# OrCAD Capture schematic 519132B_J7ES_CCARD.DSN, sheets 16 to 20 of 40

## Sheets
16 16. SOC PRG0 & PRG1: size C; rev: A
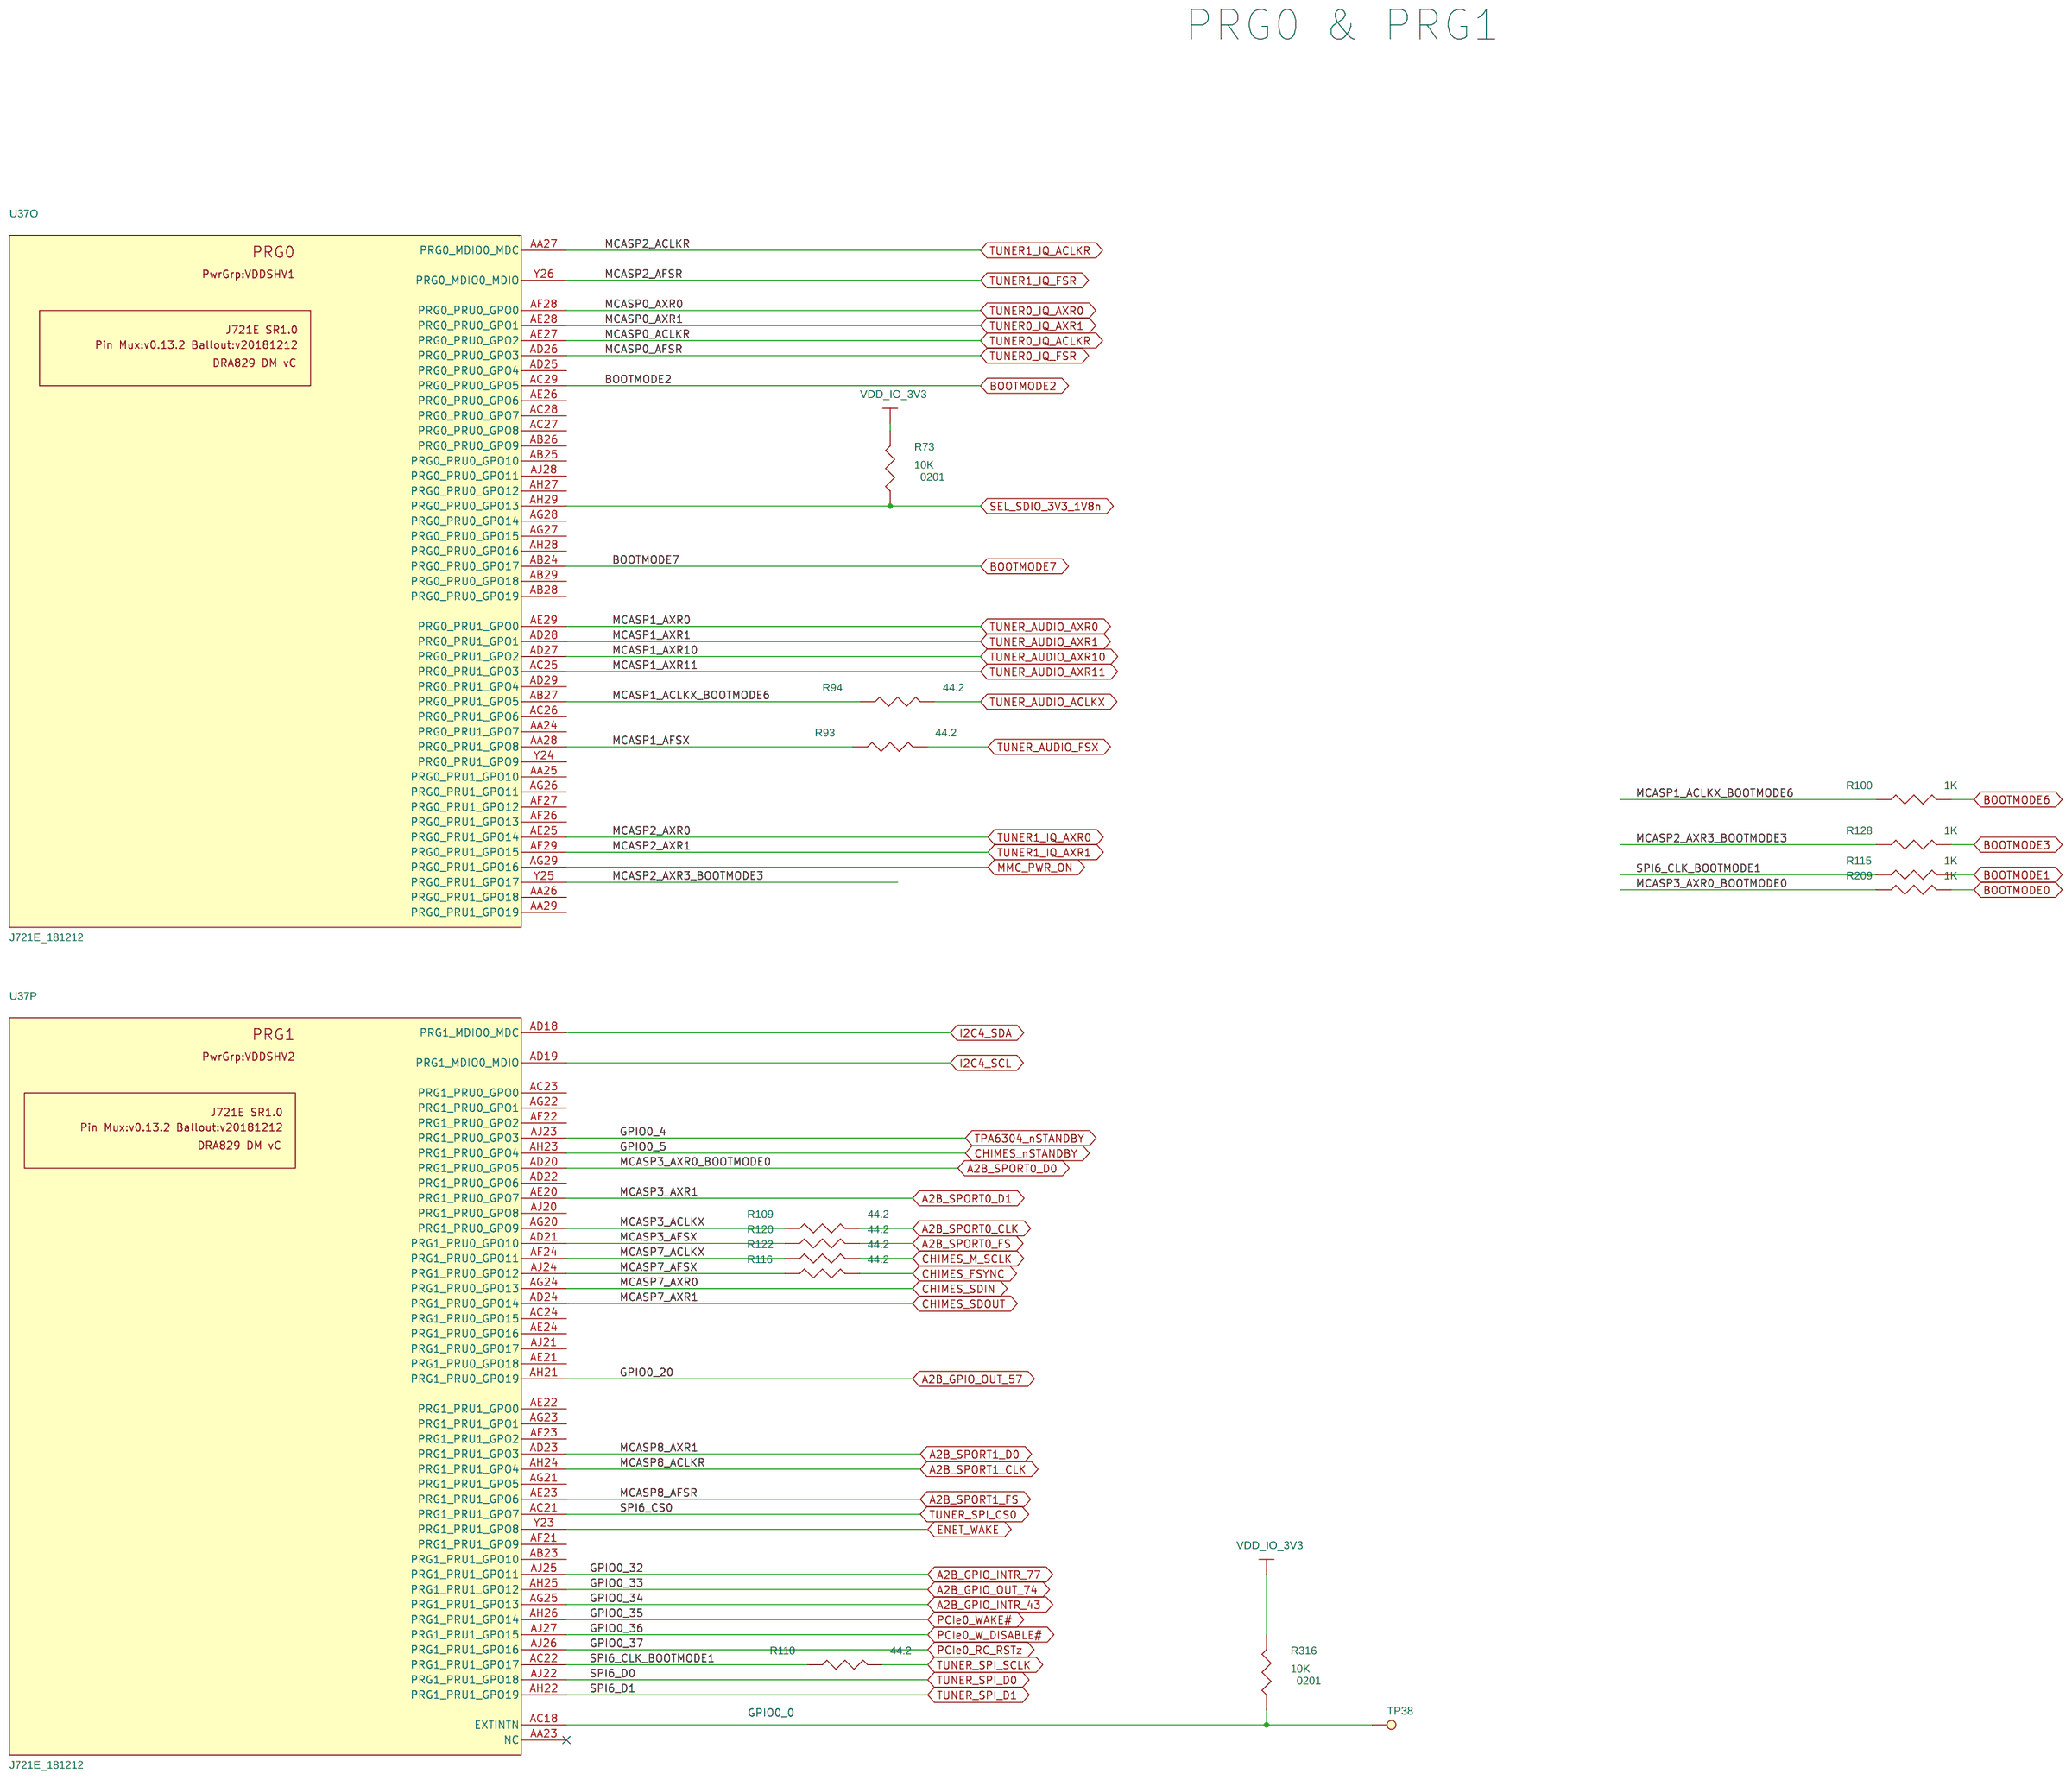
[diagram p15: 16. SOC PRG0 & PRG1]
17 17. SOC ANALOG POWER 1: size C; rev: A
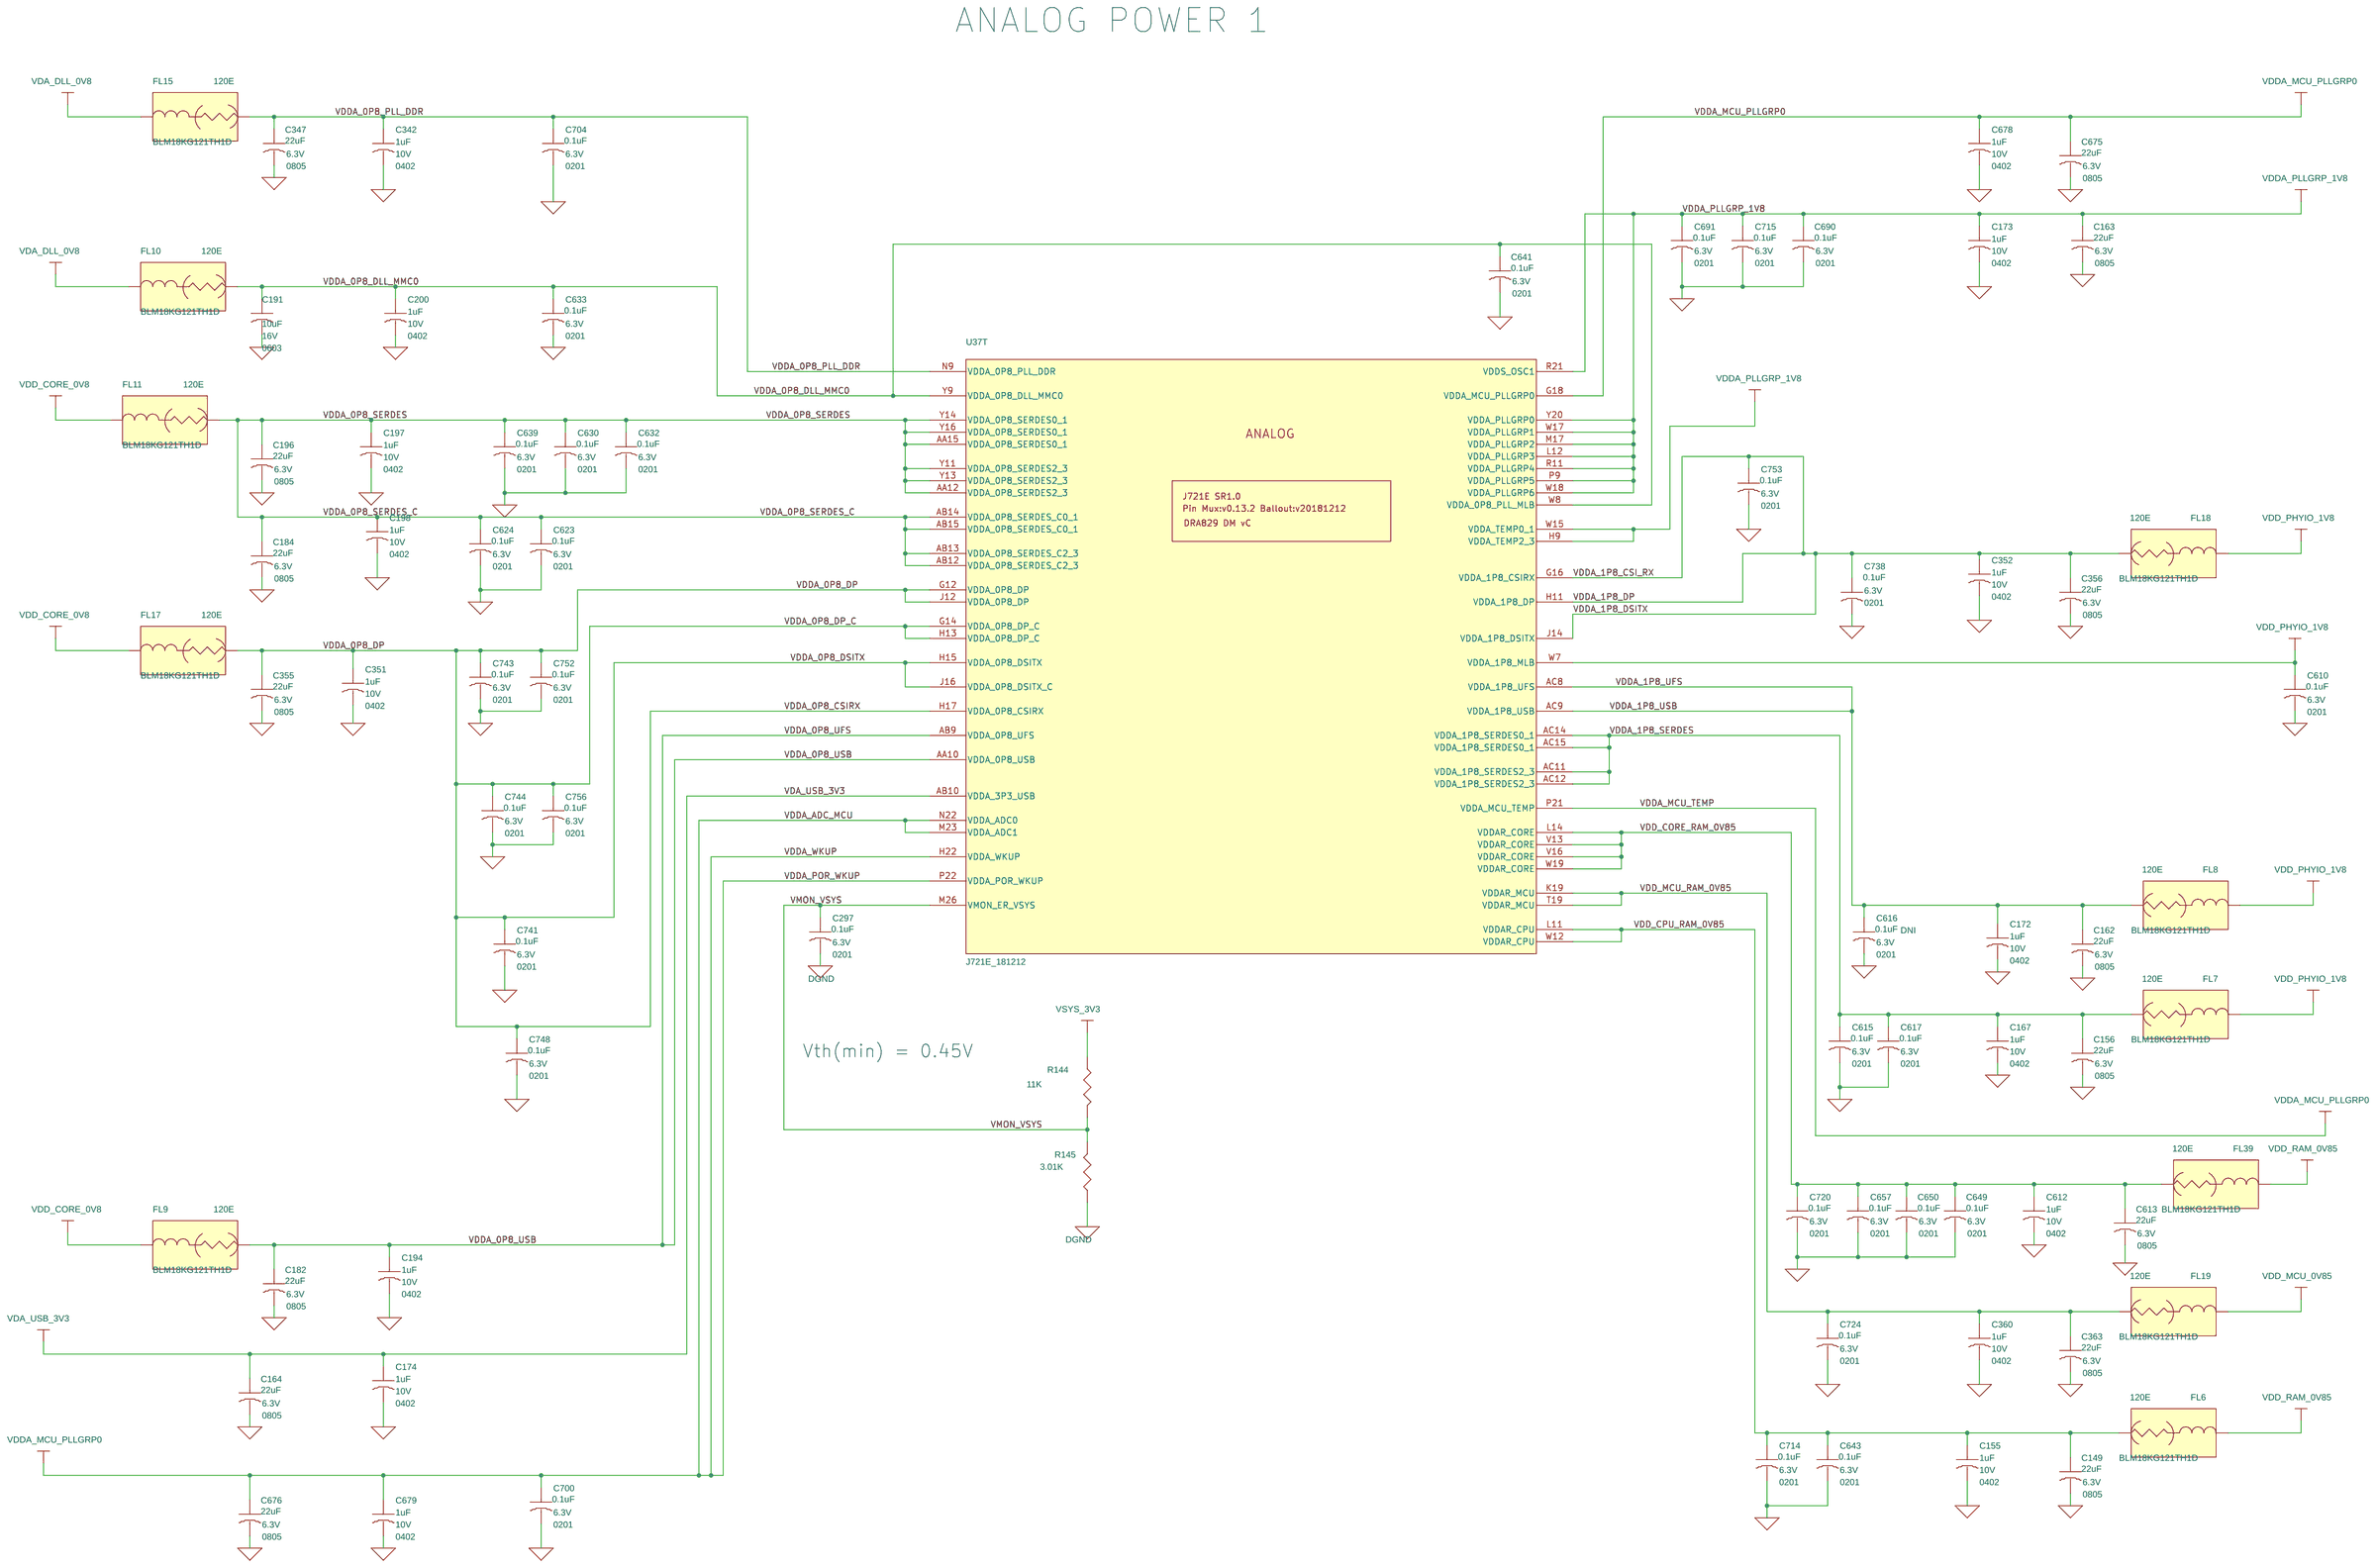
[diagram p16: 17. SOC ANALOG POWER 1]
18 18. SOC DIGITAL POWER 2: size C; rev: A
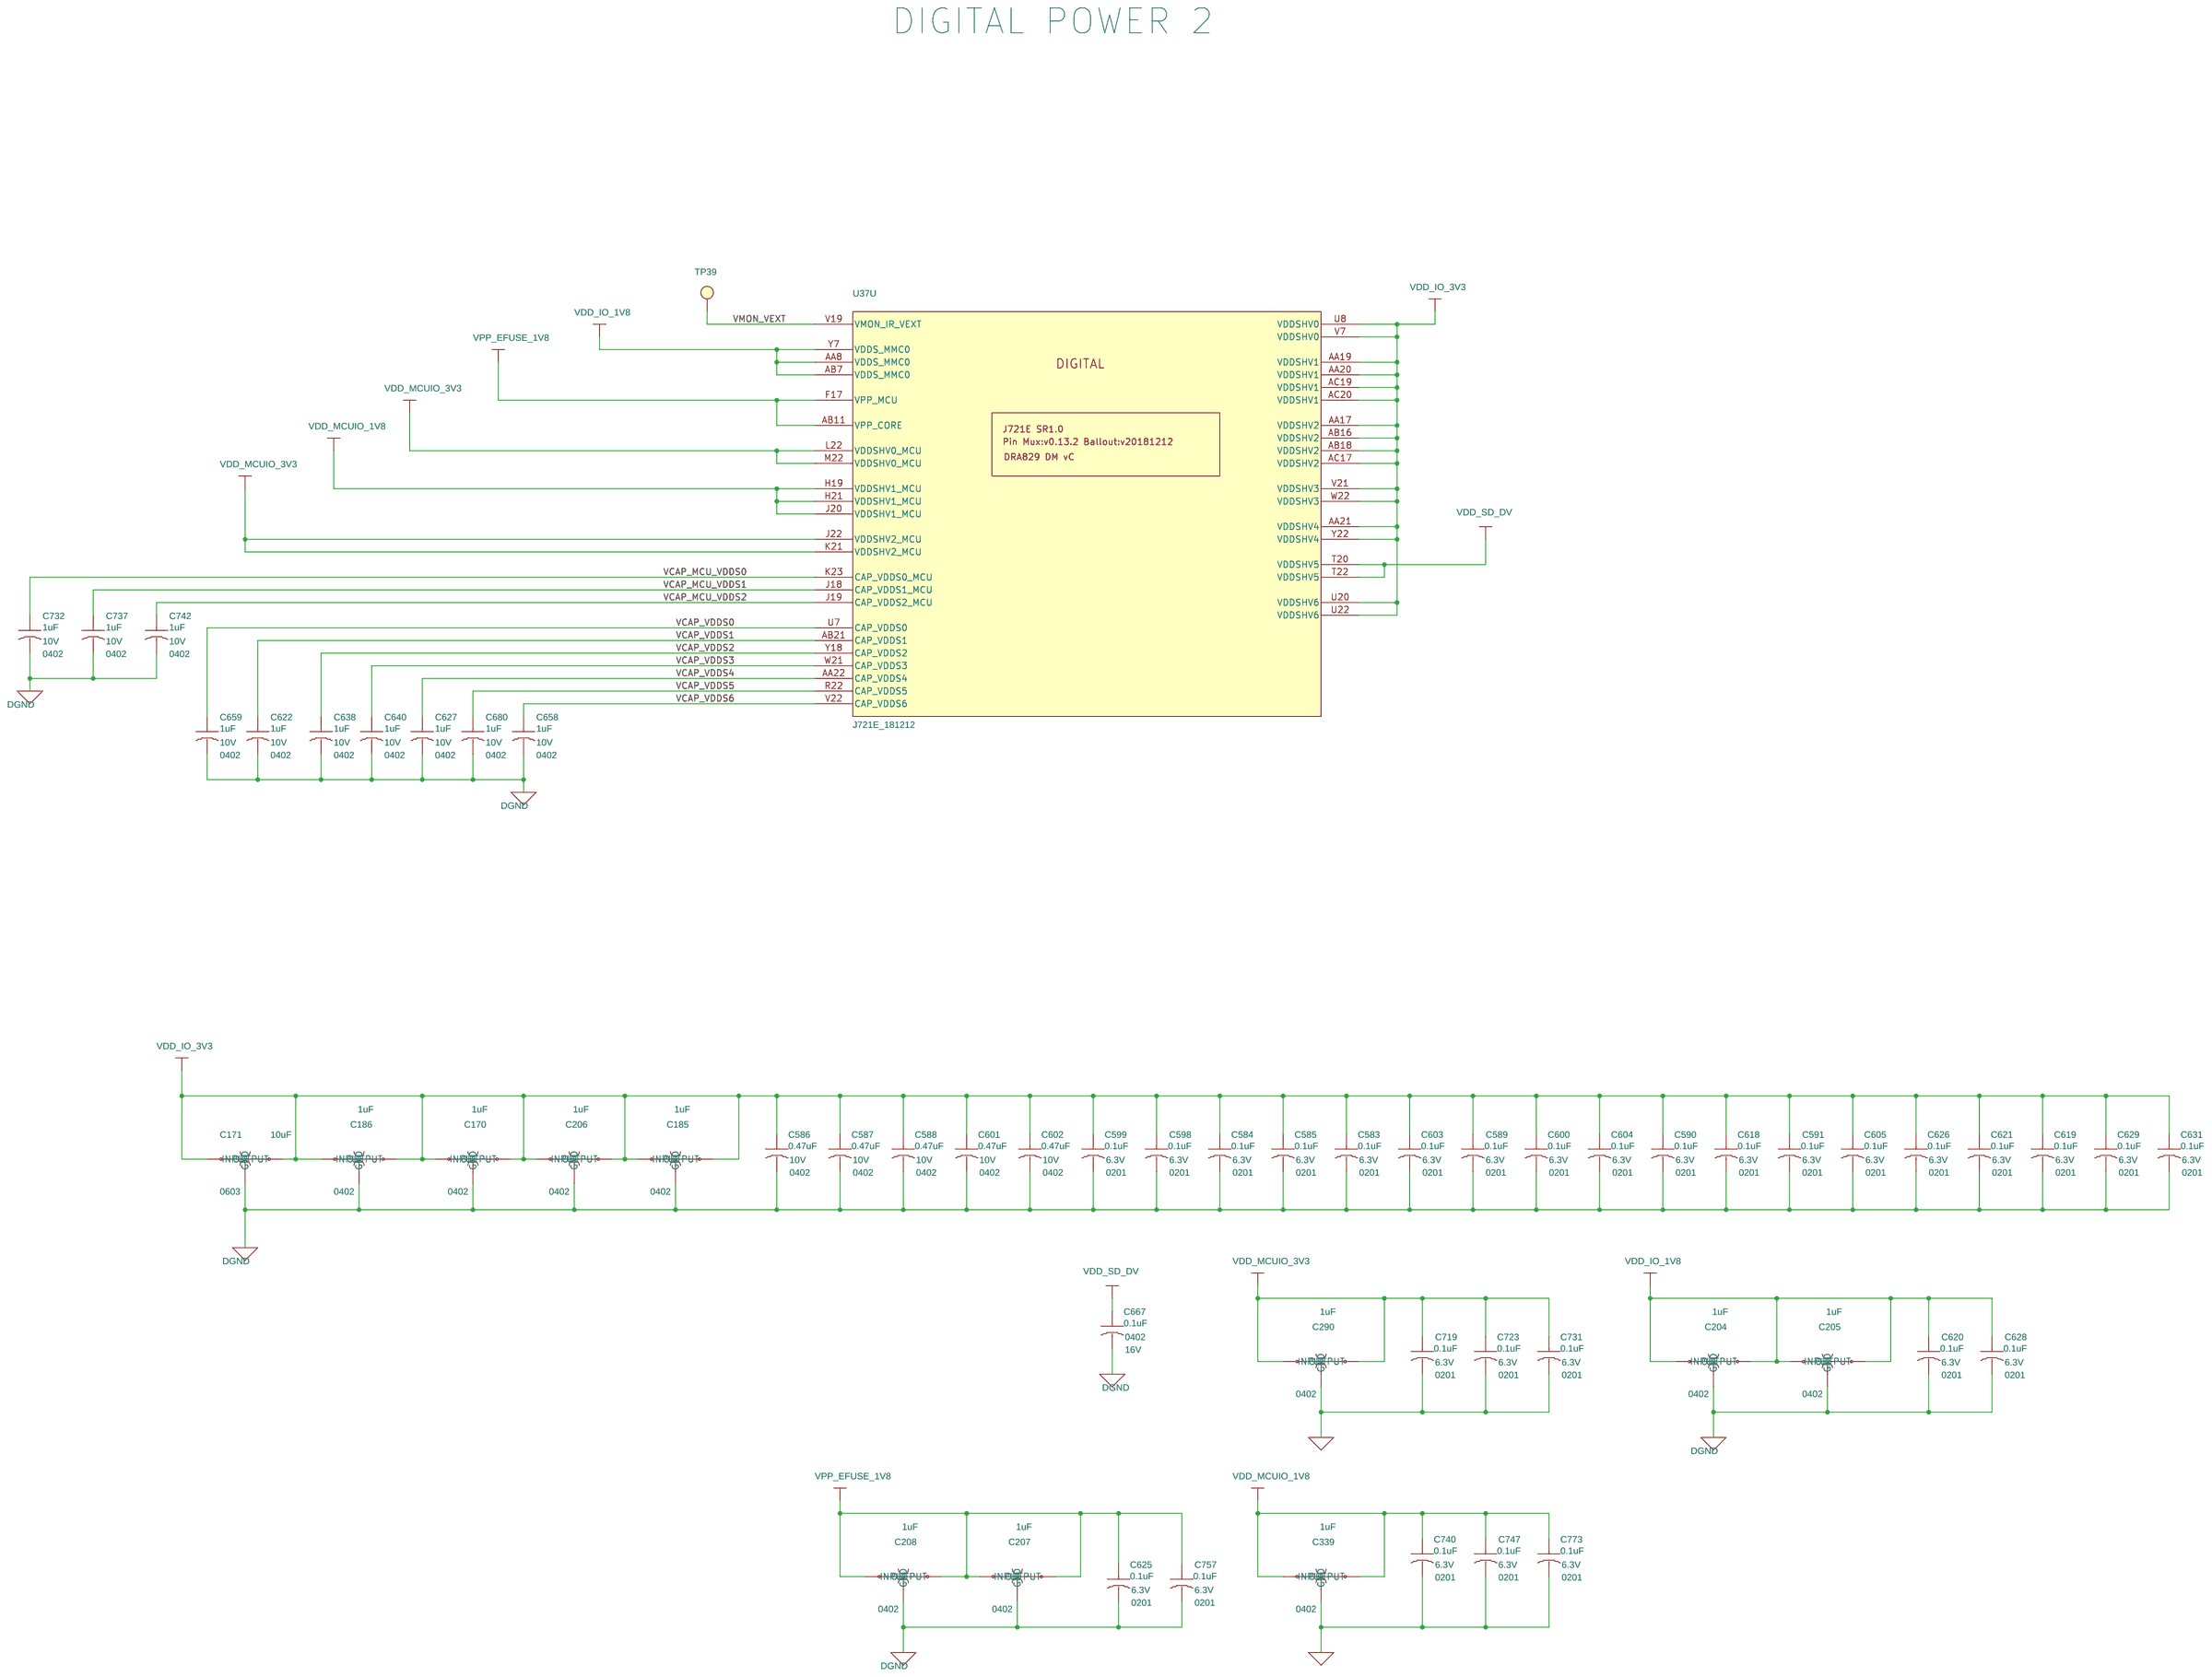
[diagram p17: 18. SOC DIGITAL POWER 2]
19 19. SOC DIGITAL POWER 3: size C; rev: A
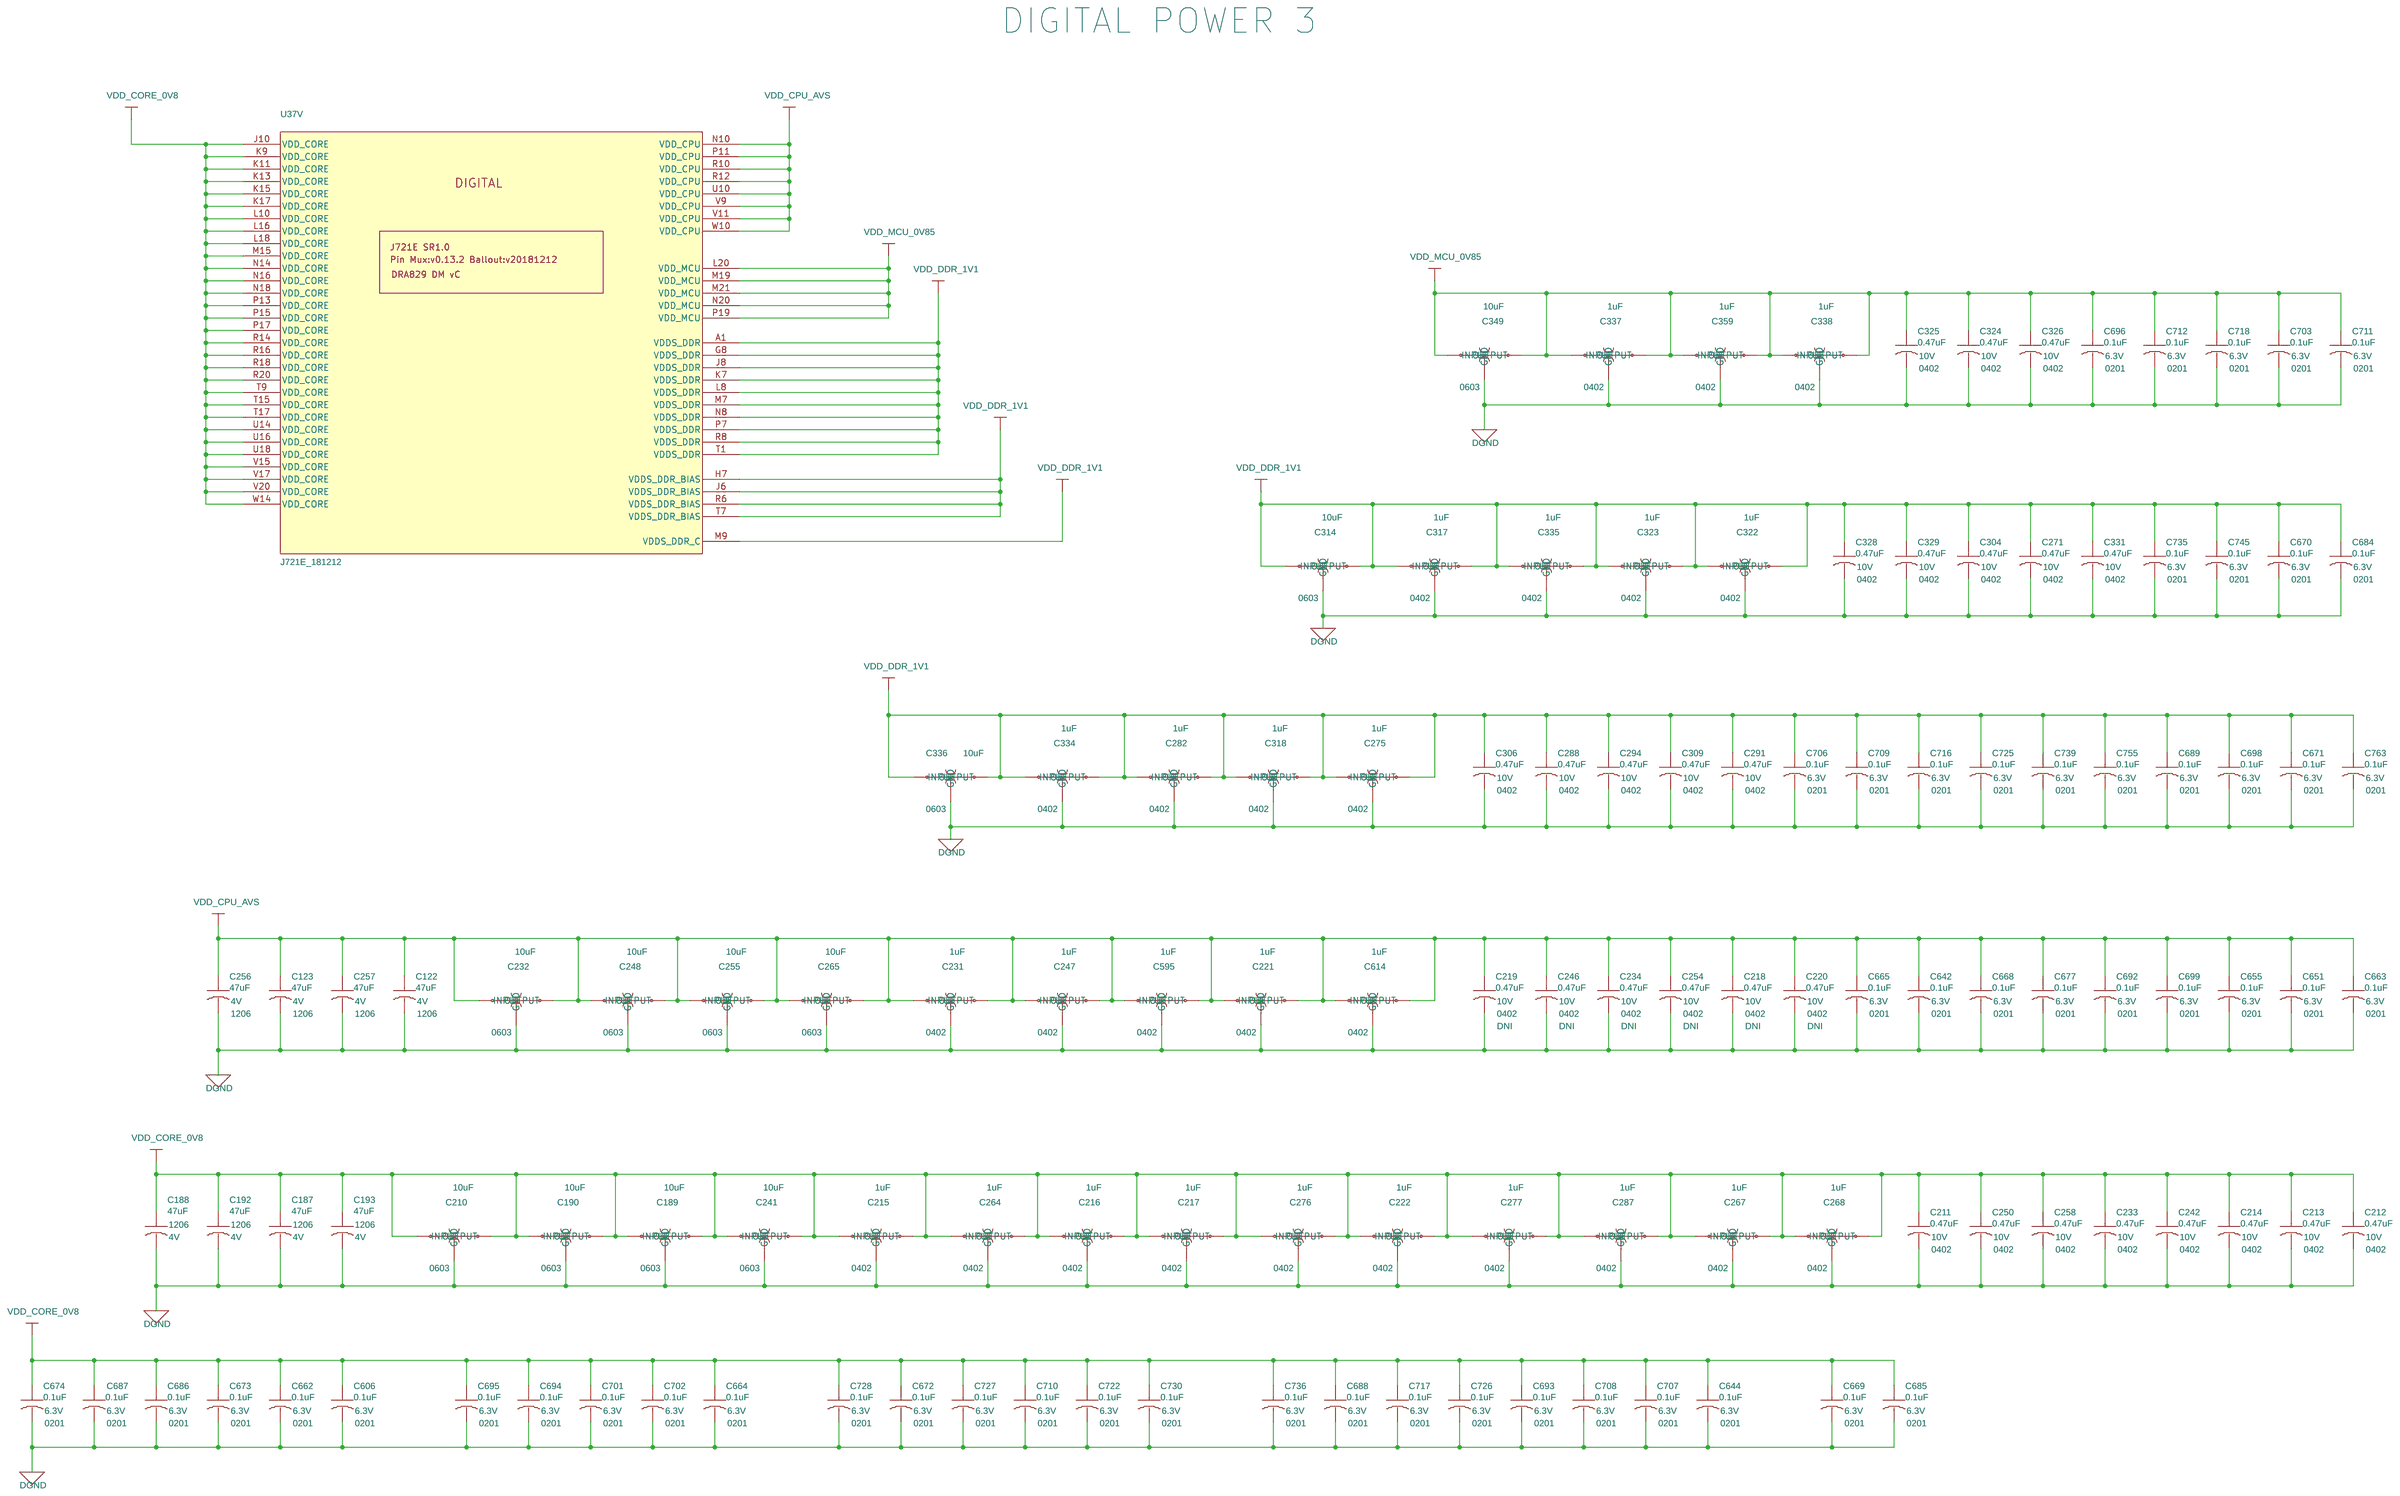
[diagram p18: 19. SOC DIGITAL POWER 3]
20 20. SOC GND: size C; rev: A
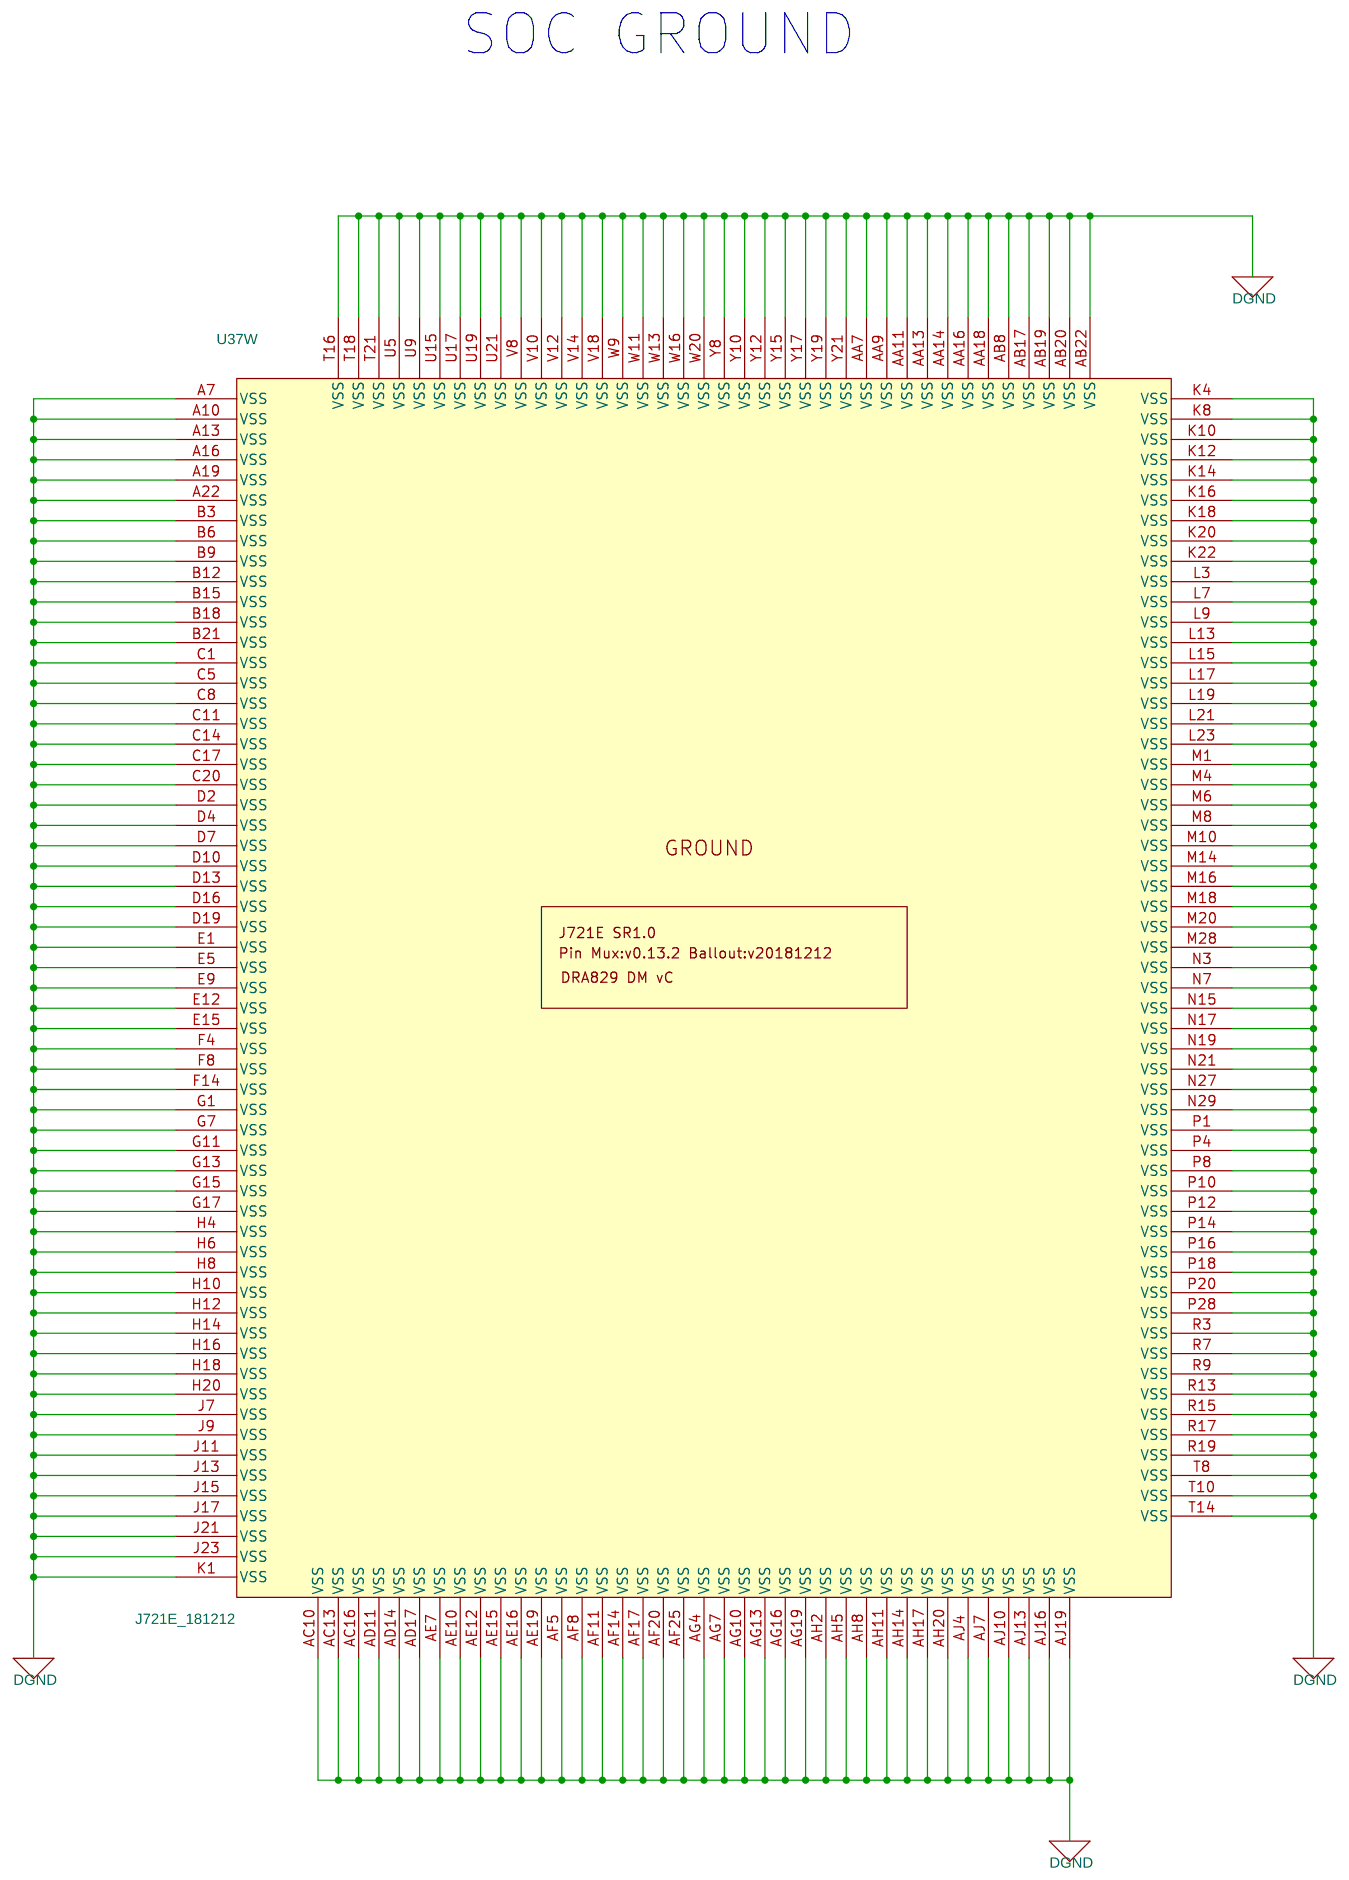
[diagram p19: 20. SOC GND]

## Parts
sheet 16. SOC PRG0 & PRG1
R73  10K  [r201-18p5x15]
R93  44.2  [r201-18p5x15]
R94  44.2  [r201-18p5x15]
R100  1K  [r201-18p5x15]
R109  44.2  [r201-18p5x15]
R110  44.2  [r201-18p5x15]
R115  1K  [r201-18p5x15]
R116  44.2  [r201-18p5x15]
R120  44.2  [r201-18p5x15]
R122  44.2  [r201-18p5x15]
R128  1K  [r201-18p5x15]
R209  1K  [r201-18p5x15]
R316  10K  [r201-18p5x15]
TP38  TP_VIA_MEM0  [tp-18RD8]
U37  J721E_181212  [FCBGA827_31-49_950X950_2-8]  (sections A,B,C,D,E,F,G,H,I,J,K,L,M,N,O,P,Q,R,S,T,U,V,W)
sheet 17. SOC ANALOG POWER 1
C149  22uF  [c805-35x60]
C155  1uF  [CAP0402_0-75]
C156  22uF  [c805-35x60]
C162  22uF  [c805-35x60]
C163  22uF  [c805-35x60]
C164  22uF  [c805-35x60]
C167  1uF  [CAP0402_0-75]
C172  1uF  [CAP0402_0-75]
C173  1uF  [CAP0402_0-75]
C174  1uF  [CAP0402_0-75]
C182  22uF  [c805-35x60]
C184  22uF  [c805-35x60]
C191  10uF  [c603-35x45]
C194  1uF  [CAP0402_0-75]
C196  22uF  [c805-35x60]
C197  1uF  [CAP0402_0-75]
C198  1uF  [CAP0402_0-75]
C200  1uF  [CAP0402_0-75]
C297  0.1uF  [c201-6p6spc]
C342  1uF  [CAP0402_0-75]
C347  22uF  [c805-35x60]
C351  1uF  [CAP0402_0-75]
C352  1uF  [CAP0402_0-75]
C355  22uF  [c805-35x60]
C356  22uF  [c805-35x60]
C360  1uF  [CAP0402_0-75]
C363  22uF  [c805-35x60]
C610  0.1uF  [c201-6p6spc]
C612  1uF  [CAP0402_0-75]
C613  22uF  [c805-35x60]
C615  0.1uF  [c201-6p6spc]
C616  0.1uF  [c201-6p6spc]
C617  0.1uF  [c201-6p6spc]
C623  0.1uF  [c201-6p6spc]
C624  0.1uF  [c201-6p6spc]
C630  0.1uF  [c201-6p6spc]
C632  0.1uF  [c201-6p6spc]
C633  0.1uF  [c201-6p6spc]
C639  0.1uF  [c201-6p6spc]
C641  0.1uF  [c201-6p6spc]
C643  0.1uF  [c201-6p6spc]
C649  0.1uF  [c201-6p6spc]
C650  0.1uF  [c201-6p6spc]
C657  0.1uF  [c201-6p6spc]
C675  22uF  [c805-35x60]
C676  22uF  [c805-35x60]
C678  1uF  [CAP0402_0-75]
C679  1uF  [CAP0402_0-75]
C690  0.1uF  [c201-6p6spc]
C691  0.1uF  [c201-6p6spc]
C700  0.1uF  [c201-6p6spc]
C704  0.1uF  [c201-6p6spc]
C714  0.1uF  [c201-6p6spc]
C715  0.1uF  [c201-6p6spc]
C720  0.1uF  [c201-6p6spc]
C724  0.1uF  [c201-6p6spc]
C738  0.1uF  [c201-6p6spc]
C741  0.1uF  [c201-6p6spc]
C743  0.1uF  [c201-6p6spc]
C744  0.1uF  [c201-6p6spc]
C748  0.1uF  [c201-6p6spc]
C752  0.1uF  [c201-6p6spc]
C753  0.1uF  [c201-6p6spc]
C756  0.1uF  [c201-6p6spc]
FL6  120E  [l603-35x45]
FL7  120E  [l603-35x45]
FL8  120E  [l603-35x45]
FL9  120E  [l603-35x45]
FL10  120E  [l603-35x45]
FL11  120E  [l603-35x45]
FL15  120E  [l603-35x45]
FL17  120E  [l603-35x45]
FL18  120E  [l603-35x45]
FL19  120E  [l603-35x45]
FL39  120E  [l603-35x45]
R144  11K  [r402-25]
R145  3.01K  [r402-25]
sheet 18. SOC DIGITAL POWER 2
C170  1uF  [EMIFIL_NFM15CC_0402_0-5]
C171  10uF  [NFM18HC]
C185  1uF  [EMIFIL_NFM15CC_0402_0-5]
C186  1uF  [EMIFIL_NFM15CC_0402_0-5]
C204  1uF  [EMIFIL_NFM15CC_0402_0-5]
C205  1uF  [EMIFIL_NFM15CC_0402_0-5]
C206  1uF  [EMIFIL_NFM15CC_0402_0-5]
C207  1uF  [EMIFIL_NFM15CC_0402_0-5]
C208  1uF  [EMIFIL_NFM15CC_0402_0-5]
C290  1uF  [EMIFIL_NFM15CC_0402_0-5]
C339  1uF  [EMIFIL_NFM15CC_0402_0-5]
C583  0.1uF  [c201-6p6spc]
C584  0.1uF  [c201-6p6spc]
C585  0.1uF  [c201-6p6spc]
C586  0.47uF  [c402-25]
C587  0.47uF  [c402-25]
C588  0.47uF  [c402-25]
C589  0.1uF  [c201-6p6spc]
C590  0.1uF  [c201-6p6spc]
C591  0.1uF  [c201-6p6spc]
C598  0.1uF  [c201-6p6spc]
C599  0.1uF  [c201-6p6spc]
C600  0.1uF  [c201-6p6spc]
C601  0.47uF  [c402-25]
C602  0.47uF  [c402-25]
C603  0.1uF  [c201-6p6spc]
C604  0.1uF  [c201-6p6spc]
C605  0.1uF  [c201-6p6spc]
C618  0.1uF  [c201-6p6spc]
C619  0.1uF  [c201-6p6spc]
C620  0.1uF  [c201-6p6spc]
C621  0.1uF  [c201-6p6spc]
C622  1uF  [c402-25]
C625  0.1uF  [c201-6p6spc]
C626  0.1uF  [c201-6p6spc]
C627  1uF  [c402-25]
C628  0.1uF  [c201-6p6spc]
C629  0.1uF  [c201-6p6spc]
C631  0.1uF  [c201-6p6spc]
C638  1uF  [c402-25]
C640  1uF  [c402-25]
C658  1uF  [c402-25]
C659  1uF  [c402-25]
C667  0.1uF  [c402-25]
C680  1uF  [c402-25]
C719  0.1uF  [c201-6p6spc]
C723  0.1uF  [c201-6p6spc]
C731  0.1uF  [c201-6p6spc]
C732  1uF  [c402-25]
C737  1uF  [c402-25]
C740  0.1uF  [c201-6p6spc]
C742  1uF  [c402-25]
C747  0.1uF  [c201-6p6spc]
C757  0.1uF  [c201-6p6spc]
C773  0.1uF  [c201-6p6spc]
TP39  TP40_SMD  [TP40_SMD]
sheet 19. SOC DIGITAL POWER 3
C122  47uF  [C1206-40X70]
C123  47uF  [C1206-40X70]
C187  47uF  [C1206-40X70]
C188  47uF  [C1206-40X70]
C189  10uF  [NFM18HC]
C190  10uF  [NFM18HC]
C192  47uF  [C1206-40X70]
C193  47uF  [C1206-40X70]
C210  10uF  [NFM18HC]
C211  0.47uF  [c402-25]
C212  0.47uF  [c402-25]
C213  0.47uF  [c402-25]
C214  0.47uF  [c402-25]
C215  1uF  [EMIFIL_NFM15CC_0402_0-5]
C216  1uF  [EMIFIL_NFM15CC_0402_0-5]
C217  1uF  [EMIFIL_NFM15CC_0402_0-5]
C218  0.47uF  [c402-25]
C219  0.47uF  [c402-25]
C220  0.47uF  [c402-25]
C221  1uF  [EMIFIL_NFM15CC_0402_0-5]
C222  1uF  [EMIFIL_NFM15CC_0402_0-5]
C231  1uF  [EMIFIL_NFM15CC_0402_0-5]
C232  10uF  [NFM18HC]
C233  0.47uF  [c402-25]
C234  0.47uF  [c402-25]
C241  10uF  [NFM18HC]
C242  0.47uF  [c402-25]
C246  0.47uF  [c402-25]
C247  1uF  [EMIFIL_NFM15CC_0402_0-5]
C248  10uF  [NFM18HC]
C250  0.47uF  [c402-25]
C254  0.47uF  [c402-25]
C255  10uF  [NFM18HC]
C256  47uF  [C1206-40X70]
C257  47uF  [C1206-40X70]
C258  0.47uF  [c402-25]
C264  1uF  [EMIFIL_NFM15CC_0402_0-5]
C265  10uF  [NFM18HC]
C267  1uF  [EMIFIL_NFM15CC_0402_0-5]
C268  1uF  [EMIFIL_NFM15CC_0402_0-5]
C271  0.47uF  [c402-25]
C275  1uF  [EMIFIL_NFM15CC_0402_0-5]
C276  1uF  [EMIFIL_NFM15CC_0402_0-5]
C277  1uF  [EMIFIL_NFM15CC_0402_0-5]
C282  1uF  [EMIFIL_NFM15CC_0402_0-5]
C287  1uF  [EMIFIL_NFM15CC_0402_0-5]
C288  0.47uF  [c402-25]
C291  0.47uF  [c402-25]
C294  0.47uF  [c402-25]
C304  0.47uF  [c402-25]
C306  0.47uF  [c402-25]
C309  0.47uF  [c402-25]
C314  10uF  [NFM18HC]
C317  1uF  [EMIFIL_NFM15CC_0402_0-5]
C318  1uF  [EMIFIL_NFM15CC_0402_0-5]
C322  1uF  [EMIFIL_NFM15CC_0402_0-5]
C323  1uF  [EMIFIL_NFM15CC_0402_0-5]
C324  0.47uF  [c402-25]
C325  0.47uF  [c402-25]
C326  0.47uF  [c402-25]
C328  0.47uF  [c402-25]
C329  0.47uF  [c402-25]
C331  0.47uF  [c402-25]
C334  1uF  [EMIFIL_NFM15CC_0402_0-5]
C335  1uF  [EMIFIL_NFM15CC_0402_0-5]
C336  10uF  [NFM18HC]
C337  1uF  [EMIFIL_NFM15CC_0402_0-5]
C338  1uF  [EMIFIL_NFM15CC_0402_0-5]
C349  10uF  [NFM18HC]
C359  1uF  [EMIFIL_NFM15CC_0402_0-5]
C595  1uF  [EMIFIL_NFM15CC_0402_0-5]
C606  0.1uF  [c201-6p6spc]
C614  1uF  [EMIFIL_NFM15CC_0402_0-5]
C642  0.1uF  [c201-6p6spc]
C644  0.1uF  [c201-6p6spc]
C651  0.1uF  [c201-6p6spc]
C655  0.1uF  [c201-6p6spc]
C662  0.1uF  [c201-6p6spc]
C663  0.1uF  [c201-6p6spc]
C664  0.1uF  [c201-6p6spc]
C665  0.1uF  [c201-6p6spc]
C668  0.1uF  [c201-6p6spc]
C669  0.1uF  [c201-6p6spc]
C670  0.1uF  [c201-6p6spc]
C671  0.1uF  [c201-6p6spc]
C672  0.1uF  [c201-6p6spc]
C673  0.1uF  [c201-6p6spc]
C674  0.1uF  [c201-6p6spc]
C677  0.1uF  [c201-6p6spc]
C684  0.1uF  [c201-6p6spc]
C685  0.1uF  [c201-6p6spc]
C686  0.1uF  [c201-6p6spc]
C687  0.1uF  [c201-6p6spc]
C688  0.1uF  [c201-6p6spc]
C689  0.1uF  [c201-6p6spc]
C692  0.1uF  [c201-6p6spc]
C693  0.1uF  [c201-6p6spc]
C694  0.1uF  [c201-6p6spc]
C695  0.1uF  [c201-6p6spc]
C696  0.1uF  [c201-6p6spc]
C698  0.1uF  [c201-6p6spc]
C699  0.1uF  [c201-6p6spc]
C701  0.1uF  [c201-6p6spc]
C702  0.1uF  [c201-6p6spc]
C703  0.1uF  [c201-6p6spc]
C706  0.1uF  [c201-6p6spc]
C707  0.1uF  [c201-6p6spc]
C708  0.1uF  [c201-6p6spc]
C709  0.1uF  [c201-6p6spc]
C710  0.1uF  [c201-6p6spc]
C711  0.1uF  [c201-6p6spc]
C712  0.1uF  [c201-6p6spc]
C716  0.1uF  [c201-6p6spc]
C717  0.1uF  [c201-6p6spc]
C718  0.1uF  [c201-6p6spc]
C722  0.1uF  [c201-6p6spc]
C725  0.1uF  [c201-6p6spc]
C726  0.1uF  [c201-6p6spc]
C727  0.1uF  [c201-6p6spc]
C728  0.1uF  [c201-6p6spc]
C730  0.1uF  [c201-6p6spc]
C735  0.1uF  [c201-6p6spc]
C736  0.1uF  [c201-6p6spc]
C739  0.1uF  [c201-6p6spc]
C745  0.1uF  [c201-6p6spc]
C755  0.1uF  [c201-6p6spc]
C763  0.1uF  [c201-6p6spc]

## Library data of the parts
R73 R316 = RESISTOR: RES 10K 1/20W 1% 0201; Chkd/date: MANIRAJA/080519; Crtd /date: ALVY/080519; Custom_Duty: 15%; Customs_HS_Code: 85332119; Distributor_name: DIGIKEY; Distributor_part_number: 1276-3670-1-ND; Footprint Path: Y:\MIS_DATABASE\Library\ALTIUM_TOOL\PCB_FOOTPRINTS\Altium_Footprint_Lib.PcbLib; Height: 0.26MM; Library Path: Y:\MIS_DATABASE\Library\ALTIUM_TOOL\SCHEMATICS_PARTS\MS_DISCRETE_Library.schlib; Mfr_name: SAMSUNG; Mfr_part_number: RC0603F103CS; Mistral Part No: 110011040018-R; Package: 0201; Part #: 103413-1003R; Part_type: RESISTORS\FIXED; Project: BRUKER_SD820_COMMONDO; RoHS: RoHS; Temperature: -55°C+125°C; Tolerance: 1%; Voltage: NA; Wattage: 1/20W; Weight: 0.15mg; Datasheet: Y:\MIS_DATABASE\DATASHEETS\RESISTORS\SAMSUNG_RC-SER.PDF
R93 R94 R109 R110 R116 R120 R122 = R_1: Part #: 103413-4420R
R100 R115 R128 R209 = R: Part #: 103158-1002R
TP38 = TP_VIA_MEM0_0: Part #: TP-18RD8-NO-POP
U37 = J7ES-EVM_BGA827_0: IC J7ES MICROPROCESSOR BGA827; Chkd/date: MANIRAJA/151018; Crtd /date: MANIRAJA/151018; Custom_Duty: 15%; Customs_HS_Code: 85423100; Distributor_name: NA; Distributor_part_number: NA; Footprint Path: Y:\MIS_DATABASE\Library\ALTIUM_TOOL\PCB_FOOTPRINTS\Altium_Footprint_Lib.PcbLib; Height: 2.79MM; Library Path: Y:\MIS_DATABASE\Library\ALTIUM_TOOL\SCHEMATICS_PARTS\MS_MICROPROCESSOR_Library.schlib; Library Ref: J7ES-EVM_BGA827; Mfr_name: TEXAS INSTRUMENTS; Mfr_part_number: J7ES_EVM; Mistral Part No: 141218060001; Package: BGA827; Part #: 105271-0001R-TI; Part_type: ICS\DIGITAL\MICROPROCESSOR; Project: TI_J7ES_EVM_CP; RoHS: NA; Temperature: NA; Tolerance: NA; Voltage: NA; Wattage: NA; Weight: NA; Datasheet: Y:\MIS_DATABASE\DATASHEETS\ICS\DIGITAL\MICROCONTROLLER\J7ES.PDF
C149 C156 C162-C164 C182 C184 C196 C347 C355 C356 C363 C613 C675 C676 = CAP: CAP CERAMIC 22uF 6.3V 20% X7T AUTO 0805; Chkd/date: MANIRAJA/261018; Crtd /date: ALVY/251018; Custom_Duty: 15%; Customs_HS_Code: 85322990; Distributor_name: MOUSER; Distributor_part_number: 81-GCM21BD70J226ME6L; Footprint Path: Y:\MIS_DATABASE\Library\ALTIUM_TOOL\PCB_FOOTPRINTS\Altium_Footprint_Lib.PcbLib; Height: 1.25MM; Library Path: Y:\MIS_DATABASE\Library\ALTIUM_TOOL\SCHEMATICS_PARTS\MS_DISCRETE_Library.schlib; Mfr_name: MURATA; Mfr_part_number: GCM21BD70J226ME36L; Mistral Part No: 120018100065-R; Package: 0805; Part #: 105333-0221R; Part_type: CAPACITORS\CERAMIC; Project: TI_J7ES_EVM_SOM; RoHS: RoHS; Temperature: -55°C+125°C; Tolerance: 20%; Voltage: 6.3V; Wattage: NA; Weight: NA; Datasheet: Y:\MIS_DATABASE\DATASHEETS\CAPACITORS\GCM-SERIES.PDF
C155 C167 C172-C174 C194 C197 C198 C200 C342 C351 C352 C360 C612 C622 C627 C638 C640 C658 C659 C678-C680 C732 C737 C742 = CAP: CAP CERAMIC 1uF 10V 10% X7S AUTO 0402; Chkd/date: MANIRAJA/100918; Crtd /date: ALVY/100918; Custom_Duty: 15%; Customs_HS_Code: 85322990; Distributor_name: DIGIKEY; Distributor_part_number: 490-13409-1-ND; Footprint Path: Y:\MIS_DATABASE\Library\ALTIUM_TOOL\PCB_FOOTPRINTS\Altium_Footprint_Lib.PcbLib; Height: 0.70MM; Library Path: Y:\MIS_DATABASE\Library\ALTIUM_TOOL\SCHEMATICS_PARTS\MS_DISCRETE_Library.schlib; Mfr_name: MURATA; Mfr_part_number: GCM155C71A105KE38D; Mistral Part No: 120018090021-R; Package: 0402; Part #: 104911-0100R; Part_type: CAPACITORS\CERAMIC; Project: SMART-M_SCRIPTALK_PB; RoHS: RoHS; Temperature: -55°C+125°C; Tolerance: 10%; Voltage: 10V; Wattage: NA; Weight: 6mg; Datasheet: Y:\MIS_DATABASE\DATASHEETS\CAPACITORS\MURATA-GCM-SER.PDF
C191 = CAP: CAP CERAMIC 10uF 16V 20% X6S 0603; Chkd/date: VASANTHA/170117; Crtd /date: VASANTHA/170117; Custom_Duty: 15%; Customs_HS_Code: 85322990; Distributor_name: DIGIKEY; Distributor_part_number: 490-7198-1-ND; Footprint Path: Y:\MIS_DATABASE\Library\ALTIUM_TOOL\PCB_FOOTPRINTS\Altium_Footprint_Lib.PcbLib; Height: 0.90MM; Library Path: Y:\MIS_DATABASE\Library\ALTIUM_TOOL\SCHEMATICS_PARTS\MS_DISCRETE_Library.schlib; Mfr_name: MURATA; Mfr_part_number: GRM188C81C106MA73D; Mistral Part No: 120017010004-R; Package: 0603; Part #: 105312-0101R; Part_type: CAPACITORS\CERAMIC; Project: TRMM_SMART-M_PS; RoHS: RoHS; Temperature: -55°C+105°C; Tolerance: 20%; Voltage: 16V; Wattage: NA; Weight: 6.3mg; Datasheet: Y:\MIS_DATABASE\DATASHEETS\CAPACITORS\MURATA-GXX-SER_NOV17.PDF
C297 C583-C585 C589-C591 C598-C600 C603-C606 C610 C618-C621 C625 C626 C628 C629 C631 C641 C642 C644 C651 C655 C662-C665 C668-C674 C677 C684-C689 C692-C696 C698 C699 C701-C703 C706-C712 C716-C719 C722 C723 C725-C728 C730 C731 C735 C736 C739 C740 C745 C747 C755 C757 C763 C773 = CAP: CAP CERAMIC 0.1uF 6.3V 10% X7S AUTO 0201; Chkd/date: MANIRAJA/011018; Crtd /date: MANIRAJA/011018; Custom_Duty: 15%; Customs_HS_Code: 85322990; Distributor_name: NA; Distributor_part_number: NA; Footprint Path: Y:\MIS_DATABASE\Library\ALTIUM_TOOL\PCB_FOOTPRINTS\Altium_Footprint_Lib.PcbLib; Height: 0.33MM; Library Path: Y:\MIS_DATABASE\Library\ALTIUM_TOOL\SCHEMATICS_PARTS\MS_DISCRETE_Library.schlib; Mfr_name: MURATA; Mfr_part_number: GCM033C70J104K; Mistral Part No: 120018100001-R; Package: 0201; Part #: 105047-1100R; Part_type: CAPACITORS\CERAMIC; Project: TI_J7_SVB-DUT; RoHS: RoHS; Temperature: -55°C+125°C; Tolerance: 10%; Voltage: 6.3V; Wattage: NA; Weight: NA; Datasheet: Y:\MIS_DATABASE\DATASHEETS\CAPACITORS\GCM033C70J104K.PDF
C615-C617 C623 C624 C630 C632 C633 C639 C643 C649 C650 C657 C690 C691 C700 C704 C714 C715 C720 C724 C738 C741 C743 C744 C748 C752 C753 C756 = CAP: CAP CERAMIC 0.1uF 6.3V 10% X7S AUTO 0201; Assembly_Instruction: DNI; Chkd/date: MANIRAJA/011018; Crtd /date: MANIRAJA/011018; Custom_Duty: 15%; Customs_HS_Code: 85322990; Distributor_name: NA; Distributor_part_number: NA; Footprint Path: Y:\MIS_DATABASE\Library\ALTIUM_TOOL\PCB_FOOTPRINTS\Altium_Footprint_Lib.PcbLib; Height: 0.33MM; Library Path: Y:\MIS_DATABASE\Library\ALTIUM_TOOL\SCHEMATICS_PARTS\MS_DISCRETE_Library.schlib; Mfr_name: MURATA; Mfr_part_number: GCM033C70J104K; Mistral Part No: 120018100001-R; Package: 0201; Part #: 105047-1100R; Part_type: CAPACITORS\CERAMIC; Project: TI_J7_SVB-DUT; RoHS: RoHS; Temperature: -55°C+125°C; Tolerance: 10%; Voltage: 6.3V; Wattage: NA; Weight: NA; Datasheet: Y:\MIS_DATABASE\DATASHEETS\CAPACITORS\GCM033C70J104K.PDF
FL6-FL11 FL15 FL17-FL19 FL39 = EMIFILTER_IND: IND FERRITE BEAD CHIP 120E 3A 0603; Chkd/date: MANIRAJA/251018; Crtd /date: ALVY/251018; Custom_Duty: 24%; Customs_HS_Code: 85437099; Distributor_name: DIGIKEY; Distributor_part_number: 490-13261-1-ND; Footprint Path: Y:\MIS_DATABASE\Library\ALTIUM_TOOL\PCB_FOOTPRINTS\Altium_Footprint_Lib.PcbLib; Height: 0.75MM; Library Path: Y:\MIS_DATABASE\Library\ALTIUM_TOOL\SCHEMATICS_PARTS\MS_FILTER_Library.schlib; Mfr_name: MURATA; Mfr_part_number: BLM18KG121TH1D; Mistral Part No: 130018100051-R; Package: 0603; Part #: 105269-1201R; Part_type: INDUCTOR; Project: TI_J7ES_EVM_SOM; RoHS: RoHS; Temperature: -55°C+125°C; Tolerance: 25%; Voltage: NA; Wattage: NA; Weight: 4mg; Datasheet: Y:\MIS_DATABASE\DATASHEETS\DISCRETES\INDUCTORS\BLM18XX-H1D-SER.PDF
R144 = RESISTOR: RES 11K 1/16W 1% 0402; Chkd/date: VASANTHA/251115; Crtd /date: VASANTHA/251115; Custom_Duty: 15%; Customs_HS_Code: 85332119; Distributor_name: DIGIKEY; Distributor_part_number: 311-11.0KLRCT-ND; Footprint Path: Y:\MIS_DATABASE\Library\ALTIUM_TOOL\PCB_FOOTPRINTS\Altium_Footprint_Lib.PcbLib; Height: 0.40MM; Library Path: Y:\MIS_DATABASE\Library\ALTIUM_TOOL\SCHEMATICS_PARTS\MS_DISCRETE_Library.schlib; Mfr_name: YAGEO AMERICA; Mfr_part_number: RC0402FR-0711KL; Mistral Part No: 110015110012-R; Package: 0402; Part #: 102145-1103R; Part_type: RESISTORS\FIXED; Project: TI_VLAN_SWITCH; RoHS: RoHS; Temperature: -55°C+155°C; Tolerance: 1%; Voltage: NA; Wattage: 1/16W; Weight: 0.65mg; Datasheet: Y:\MIS_DATABASE\DATASHEETS\RESISTORS\RCXXXXL-SER_MAR18.PDF
R145 = RESISTOR: RES 3K 1/16W 1% 0402; Chkd/date: MANIRAJA/101117; Crtd /date: MANIRAJA/101117; Custom_Duty: 15%; Customs_HS_Code: 85332119; Distributor_name: DIGIKEY; Distributor_part_number: 311-3KLRCT-ND; Footprint Path: Y:\MIS_DATABASE\Library\ALTIUM_TOOL\PCB_FOOTPRINTS\Altium_Footprint_Lib.PcbLib; Height: 0.40MM; Library Path: Y:\MIS_DATABASE\Library\ALTIUM_TOOL\SCHEMATICS_PARTS\MS_DISCRETE_Library.schlib; Mfr_name: YAGEO AMERICA; Mfr_part_number: RC0402FR-073KL; Mistral Part No: 110017110004-R; Package: 0402; Part #: 102145-3012R; Part_type: RESISTORS\FIXED; Project: TI_SVB_MAXWELL_DUT; RoHS: RoHS; Temperature: -55°C+155°C; Tolerance: 1%; Voltage: NA; Wattage: 1/16W; Weight: 0.65mg; Datasheet: Y:\MIS_DATABASE\DATASHEETS\RESISTORS\RCXXXXL-SER_MAR18.PDF
C170 C185 C186 C204-C208 C215-C217 C221 C222 C231 C247 C264 C267 C268 C275-C277 C282 C287 C290 C317 C318 C322 C323 C334 C335 C337-C339 C359 C595 C614 = CAP_NFM: PASSIVE FILTER EMI 1uF 4V AUTO 0402; Chkd/date: MANIRAJA/251018; Crtd /date: ALVY/251018; Custom_Duty: 15%; Customs_HS_Code: 85412900; Distributor_name: NA; Distributor_part_number: NA; Footprint Path: Y:\MIS_DATABASE\Library\ALTIUM_TOOL\PCB_FOOTPRINTS\Altium_Footprint_Lib.PcbLib; Footprint Ref: NFM15HC; Height: 0.50MM; Library Path: Y:\MIS_DATABASE\Library\ALTIUM_TOOL\SCHEMATICS_PARTS\MS_FILTER_Library.schlib; MECHANICAL 3D STEP FILE: NFM15HC; Mfr_name: MURATA; Mfr_part_number: NFM15HC105D0G; Mistral Part No: 130018100050; Package: 0402; Part #: 105251-0100R; Part_type: FILTER; Project: TI_J7ES_EVM_SOM; RoHS: NA; Temperature: NA; Tolerance: NA; Voltage: 4V; Wattage: NA; Weight: NA; Datasheet: Y:\MIS_DATABASE\DATASHEETS\DISCRETES\INDUCTORS\NFM15CC223C1A3.PDF
C171 C189 C190 C210 C232 C241 C248 C255 C265 C314 C336 C349 = CAP_NFM: PASSIVE FILTER EMI 10uF 4V AUTO 0603; Chkd/date: MANIRAJA/251018; Crtd /date: ALVY/251018; Custom_Duty: 15%; Customs_HS_Code: 85412900; Distributor_name: NA; Distributor_part_number: NA; Footprint Path: Y:\MIS_DATABASE\Library\ALTIUM_TOOL\PCB_FOOTPRINTS\Altium_Footprint_Lib.PcbLib; Height: 0.70MM; Library Path: Y:\MIS_DATABASE\Library\ALTIUM_TOOL\SCHEMATICS_PARTS\MS_FILTER_Library.schlib; Mfr_name: MURATA; Mfr_part_number: NFM18HC106D0G; Mistral Part No: 130018100049; Package: 0603; Part #: 105250-0101R; Part_type: FILTER; Project: TI_J7ES_EVM_SOM; RoHS: NA; Temperature: NA; Tolerance: NA; Voltage: 4V; Wattage: NA; Weight: NA; Datasheet: Y:\MIS_DATABASE\DATASHEETS\DISCRETES\INDUCTORS\NFM18HC-SER.PDF
C271 C288 C291 C294 C304 C306 C309 C324-C326 C328 C329 C331 C586-C588 C601 C602 = CAP: CAP CERAMIC 0.47uF 10V 10% X7S AUTO 0402; Chkd/date: MANIRAJA/280918; Crtd /date: ALVY/280918; Custom_Duty: 15%; Customs_HS_Code: 85322990; Distributor_name: DIGIKEY; Distributor_part_number: 490-14427-1-ND; Footprint Path: Y:\MIS_DATABASE\Library\ALTIUM_TOOL\PCB_FOOTPRINTS\Altium_Footprint_Lib.PcbLib; Height: 0.60MM; Library Path: Y:\MIS_DATABASE\Library\ALTIUM_TOOL\SCHEMATICS_PARTS\MS_DISCRETE_Library.schlib; Mfr_name: MURATA; Mfr_part_number: GCM155C71A474KE36D; Mistral Part No: 120018090057-R; Package: 0402; Part #: 104911-1470R; Part_type: CAPACITORS\CERAMIC; Project: TI_J7_SVB-DUT; RoHS: RoHS; Temperature: -55°C+125°C; Tolerance: 10%; Voltage: 10V; Wattage: NA; Weight: 6mg; Datasheet: Y:\MIS_DATABASE\DATASHEETS\CAPACITORS\GCM155C71A474KE36D.PDF
C667 = CAP: CAP CERAMIC 0.1uF 16V 5% X7R AUTO 0402; Chkd/date: MANIRAJA/241018; Crtd /date: ALVY/241018; Custom_Duty: 15%; Customs_HS_Code: 85322990; Distributor_name: DIGIKEY; Distributor_part_number: 490-16433-1-ND; Footprint Path: Y:\MIS_DATABASE\Library\ALTIUM_TOOL\PCB_FOOTPRINTS\Altium_Footprint_Lib.PcbLib; Height: 0.55MM; Library Path: Y:\MIS_DATABASE\Library\ALTIUM_TOOL\SCHEMATICS_PARTS\MS_DISCRETE_Library.schlib; Mfr_name: MURATA; Mfr_part_number: GCM155R71C104JA55D; Mistral Part No: 120018100055-R; Package: 0402; Part #: 104446-1100R; Part_type: CAPACITORS\CERAMIC; Project: TI_J7ES_EVM_CP; RoHS: RoHS; Temperature: -55°C+125°C; Tolerance: 5%; Voltage: 16V; Wattage: NA; Weight: 6mg; Datasheet: Y:\MIS_DATABASE\DATASHEETS\CAPACITORS\GCM155R71C104JA55D.PDF
TP39 = TESTPOINT: TESTPOINT CIR 40 SMD; Chkd/date: MAZHAR/190505; Crtd /date: MAZHAR/190505; Distributor_name: NA; Distributor_part_number: NA; Footprint Path: Y:\MIS_DATABASE\Library\ALTIUM_TOOL\PCB_FOOTPRINTS\Altium_Footprint_Lib.PcbLib; Height: NA; Library Path: Y:\MIS_DATABASE\Library\ALTIUM_TOOL\SCHEMATICS_PARTS\MS_DISCRETE_Library.schlib; MECHANICAL 3D STEP FILE: NA; Mfr_name: LOCAL; Mistral Part No: 130009030933; Package: SMD; Part #: NOPOP; Project: RAINIER-3; RoHS: NA; Temperature: NA; Tolerance: NA; Voltage: NA; Wattage: NA; Weight: NA; Datasheet: NA
C122 C123 C187 C188 C192 C193 C256 C257 = CAP: CAP CERAMIC 47uF 4V 20% X7T 1206; Chkd/date: MANIRAJA/301118; Crtd /date: ALVY/301118; Custom_Duty: 15%; Customs_HS_Code: 85322990; Distributor_name: NA; Distributor_part_number: NA; Footprint Path: Y:\MIS_DATABASE\Library\ALTIUM_TOOL\PCB_FOOTPRINTS\Altium_Footprint_Lib.PcbLib; Height: 1.90MM; Library Path: Y:\MIS_DATABASE\Library\ALTIUM_TOOL\SCHEMATICS_PARTS\MS_DISCRETE_Library.schlib; Mfr_name: MURATA; Mfr_part_number: GCM31CD70G476ME; Mistral Part No: 120018110006; Package: 1206; Part #: 105267-0471R; Part_type: CAPACITORS\CERAMIC; Project: TI_J7ES_EVM_SOM; RoHS: NA; Temperature: NA; Tolerance: 20%; Voltage: 4V; Wattage: NA; Weight: NA; Datasheet: Y:\MIS_DATABASE\DATASHEETS\CAPACITORS\GCM31CD70G476ME.PDF
C211-C214 C218-C220 C233 C234 C242 C246 C250 C254 C258 = CAP: CAP CERAMIC 0.47uF 10V 10% X7S AUTO 0402; Assembly_Instruction: DNI; Chkd/date: MANIRAJA/280918; Crtd /date: ALVY/280918; Custom_Duty: 15%; Customs_HS_Code: 85322990; Distributor_name: DIGIKEY; Distributor_part_number: 490-14427-1-ND; Footprint Path: Y:\MIS_DATABASE\Library\ALTIUM_TOOL\PCB_FOOTPRINTS\Altium_Footprint_Lib.PcbLib; Height: 0.60MM; Library Path: Y:\MIS_DATABASE\Library\ALTIUM_TOOL\SCHEMATICS_PARTS\MS_DISCRETE_Library.schlib; Mfr_name: MURATA; Mfr_part_number: GCM155C71A474KE36D; Mistral Part No: 120018090057-R; Package: 0402; Part #: 104911-1470R; Part_type: CAPACITORS\CERAMIC; Project: TI_J7_SVB-DUT; RoHS: RoHS; Temperature: -55°C+125°C; Tolerance: 10%; Voltage: 10V; Wattage: NA; Weight: 6mg; Datasheet: Y:\MIS_DATABASE\DATASHEETS\CAPACITORS\GCM155C71A474KE36D.PDF

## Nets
DGND: C122.2 C123.2 C149.2 C155.2 C156.2 C162.2 C163.2 C164.2 C167.2 C170.2(GND) C171.2(GND) C172.2 C173.2 C174.2 C182.2 C184.2 C185.2(GND) C186.2(GND) C187.2 C188.2 C189.2(GND) C190.2(GND) C191.2 C192.2 C193.2 C194.2 C196.2 C197.2 C198.2 C200.2 C204.2(GND) C205.2(GND) C206.2(GND) C207.2(GND) C208.2(GND) C210.2(GND) C211.2 C212.2 C213.2 C214.2 C215.2(GND) C216.2(GND) C217.2(GND) C218.2 C219.2 C220.2 C221.2(GND) C222.2(GND) C231.2(GND) C232.2(GND) C233.2 C234.2 C241.2(GND) C242.2 C246.2 C247.2(GND) C248.2(GND) C250.2 C254.2 C255.2(GND) C256.2 C257.2 C258.2 C264.2(GND) C265.2(GND) C267.2(GND) C268.2(GND) C271.2 C275.2(GND) C276.2(GND) C277.2(GND) C282.2(GND) C287.2(GND) C288.2 C290.2(GND) C291.2 C294.2 C297.2 C304.2 C306.2 C309.2 C314.2(GND) C317.2(GND) C318.2(GND) C322.2(GND) C323.2(GND) C324.2 C325.2 C326.2 C328.2 C329.2 C331.2 C334.2(GND) C335.2(GND) C336.2(GND) C337.2(GND) C338.2(GND) C339.2(GND) C342.2 C347.2 C349.2(GND) C351.2 C352.2 C355.2 C356.2 C359.2(GND) C360.2 C363.2 C583.2 C584.2 C585.2 C586.2 C587.2 C588.2 C589.2 C590.2 C591.2 C595.2(GND) C598.2 C599.2 C600.2 C601.2 C602.2 C603.2 C604.2 C605.2 C606.2 C610.2 C612.2 C613.2 C614.2(GND) C615.2 C616.2 C617.2 C618.2 C619.2 C620.2 C621.2 C622.2 C623.2 C624.2 C625.2 C626.2 C627.2 C628.2 C629.2 C630.2 C631.2 C632.2 C633.2 C638.2 C639.2 C640.2 C641.2 C642.2 C643.2 C644.2 C649.2 C650.2 C651.2 C655.2 C657.2 C658.2 C659.2 C662.2 C663.2 C664.2 C665.2 C667.2 C668.2 C669.2 C670.2 C671.2 C672.2 C673.2 C674.2 C675.2 C676.2 C677.2 C678.2 C679.2 C680.2 C684.2 C685.2 C686.2 C687.2 C688.2 C689.2 C690.2 C691.2 C692.2 C693.2 C694.2 C695.2 C696.2 C698.2 C699.2 C700.2 C701.2 C702.2 C703.2 C704.2 C706.2 C707.2 C708.2 C709.2 C710.2 C711.2 C712.2 C714.2 C715.2 C716.2 C717.2 C718.2 C719.2 C720.2 C722.2 C723.2 C724.2 C725.2 C726.2 C727.2 C728.2 C730.2 C731.2 C732.2 C735.2 C736.2 C737.2 C738.2 C739.2 C740.2 C741.2 C742.2 C743.2 C744.2 C745.2 C747.2 C748.2 C752.2 C753.2 C755.2 C756.2 C757.2 C763.2 C773.2 R145.2 U37.A7(VSS) U37.A10(VSS) U37.A13(VSS) U37.A16(VSS) U37.A19(VSS) U37.A22(VSS) U37.AA7(VSS) U37.AA9(VSS) U37.AA11(VSS) U37.AA13(VSS) U37.AA14(VSS) U37.AA16(VSS) U37.AA18(VSS) U37.AB8(VSS) U37.AB17(VSS) U37.AB19(VSS) U37.AB20(VSS) U37.AB22(VSS) U37.AC10(VSS) U37.AC13(VSS) U37.AC16(VSS) U37.AD11(VSS) U37.AD14(VSS) U37.AD17(VSS) U37.AE7(VSS) U37.AE10(VSS) U37.AE12(VSS) U37.AE15(VSS) U37.AE16(VSS) U37.AE19(VSS) U37.AF5(VSS) U37.AF8(VSS) U37.AF11(VSS) U37.AF14(VSS) U37.AF17(VSS) U37.AF20(VSS) U37.AF25(VSS) U37.AG4(VSS) U37.AG7(VSS) U37.AG10(VSS) U37.AG13(VSS) U37.AG16(VSS) U37.AG19(VSS) U37.AH2(VSS) U37.AH5(VSS) U37.AH8(VSS) U37.AH11(VSS) U37.AH14(VSS) U37.AH17(VSS) U37.AH20(VSS) U37.AJ4(VSS) U37.AJ7(VSS) U37.AJ10(VSS) U37.AJ13(VSS) U37.AJ16(VSS) U37.AJ19(VSS) U37.B3(VSS) U37.B6(VSS) U37.B9(VSS) U37.B12(VSS) U37.B15(VSS) U37.B18(VSS) U37.B21(VSS) U37.C1(VSS) U37.C5(VSS) U37.C8(VSS) U37.C11(VSS) U37.C14(VSS) U37.C17(VSS) U37.C20(VSS) U37.D2(VSS) U37.D4(VSS) U37.D7(VSS) U37.D10(VSS) U37.D13(VSS) U37.D16(VSS) U37.D19(VSS) U37.E1(VSS) U37.E5(VSS) U37.E9(VSS) U37.E12(VSS) U37.E15(VSS) U37.F4(VSS) U37.F8(VSS) U37.F14(VSS) U37.G1(VSS) U37.G7(VSS) U37.G11(VSS) U37.G13(VSS) U37.G15(VSS) U37.G17(VSS) U37.H4(VSS) U37.H6(VSS) U37.H8(VSS) U37.H10(VSS) U37.H12(VSS) U37.H14(VSS) U37.H16(VSS) U37.H18(VSS) U37.H20(VSS) U37.J7(VSS) U37.J9(VSS) U37.J11(VSS) U37.J13(VSS) U37.J15(VSS) U37.J17(VSS) U37.J21(VSS) U37.J23(VSS) U37.K1(VSS) U37.K4(VSS) U37.K8(VSS) U37.K10(VSS) U37.K12(VSS) U37.K14(VSS) U37.K16(VSS) U37.K18(VSS) U37.K20(VSS) U37.K22(VSS) U37.L3(VSS) U37.L7(VSS) U37.L9(VSS) U37.L13(VSS) U37.L15(VSS) U37.L17(VSS) U37.L19(VSS) U37.L21(VSS) U37.L23(VSS) U37.M1(VSS) U37.M4(VSS) U37.M6(VSS) U37.M8(VSS) U37.M10(VSS) U37.M14(VSS) U37.M16(VSS) U37.M18(VSS) U37.M20(VSS) U37.M28(VSS) U37.N3(VSS) U37.N7(VSS) U37.N15(VSS) U37.N17(VSS) U37.N19(VSS) U37.N21(VSS) U37.N27(VSS) U37.N29(VSS) U37.P1(VSS) U37.P4(VSS) U37.P8(VSS) U37.P10(VSS) U37.P12(VSS) U37.P14(VSS) U37.P16(VSS) U37.P18(VSS) U37.P20(VSS) U37.P28(VSS) U37.R3(VSS) U37.R7(VSS) U37.R9(VSS) U37.R13(VSS) U37.R15(VSS) U37.R17(VSS) U37.R19(VSS) U37.T8(VSS) U37.T10(VSS) U37.T14(VSS) U37.T16(VSS) U37.T18(VSS) U37.T21(VSS) U37.U5(VSS) U37.U9(VSS) U37.U15(VSS) U37.U17(VSS) U37.U19(VSS) U37.U21(VSS) U37.V8(VSS) U37.V10(VSS) U37.V12(VSS) U37.V14(VSS) U37.V18(VSS) U37.W9(VSS) U37.W11(VSS) U37.W13(VSS) U37.W16(VSS) U37.W20(VSS) U37.Y8(VSS) U37.Y10(VSS) U37.Y12(VSS) U37.Y15(VSS) U37.Y17(VSS) U37.Y19(VSS) U37.Y21(VSS) ; also on sheet 8 9 10 11 12 13 14 15 21 22 23 24 25 26 27 28 29 30 31 32 33 34 35 36 37 38 39 40
VDD_CORE_0V8: C187.1 C188.1 C189.1(INPUT) C189.3(OUTPUT) C190.1(INPUT) C190.3(OUTPUT) C192.1 C193.1 C210.1(INPUT) C210.3(OUTPUT) C211.1 C212.1 C213.1 C214.1 C215.1(INPUT) C215.3(OUTPUT) C216.1(INPUT) C216.3(OUTPUT) C217.1(INPUT) C217.3(OUTPUT) C222.1(INPUT) C222.3(OUTPUT) C233.1 C241.1(INPUT) C241.3(OUTPUT) C242.1 C250.1 C258.1 C264.1(INPUT) C264.3(OUTPUT) C267.1(INPUT) C267.3(OUTPUT) C268.1(INPUT) C268.3(OUTPUT) C276.1(INPUT) C276.3(OUTPUT) C277.1(INPUT) C277.3(OUTPUT) C287.1(INPUT) C287.3(OUTPUT) C606.1 C644.1 C662.1 C664.1 C669.1 C672.1 C673.1 C674.1 C685.1 C686.1 C687.1 C688.1 C693.1 C694.1 C695.1 C701.1 C702.1 C707.1 C708.1 C710.1 C717.1 C722.1 C726.1 C727.1 C728.1 C730.1 C736.1 FL9.1 FL11.1 FL17.1 U37.J10(VDD_CORE) U37.K9(VDD_CORE) U37.K11(VDD_CORE) U37.K13(VDD_CORE) U37.K15(VDD_CORE) U37.K17(VDD_CORE) U37.L10(VDD_CORE) U37.L16(VDD_CORE) U37.L18(VDD_CORE) U37.M15(VDD_CORE) U37.N14(VDD_CORE) U37.N16(VDD_CORE) U37.N18(VDD_CORE) U37.P13(VDD_CORE) U37.P15(VDD_CORE) U37.P17(VDD_CORE) U37.R14(VDD_CORE) U37.R16(VDD_CORE) U37.R18(VDD_CORE) U37.R20(VDD_CORE) U37.T9(VDD_CORE) U37.T15(VDD_CORE) U37.T17(VDD_CORE) U37.U14(VDD_CORE) U37.U16(VDD_CORE) U37.U18(VDD_CORE) U37.V15(VDD_CORE) U37.V17(VDD_CORE) U37.V20(VDD_CORE) U37.W14(VDD_CORE) ; also on sheet 24
VDD_CORE_RAM_0V85: C612.1 C613.1 C649.1 C650.1 C657.1 C720.1 FL39.2 U37.L14(VDDAR_CORE) U37.V13(VDDAR_CORE) U37.V16(VDDAR_CORE) U37.W19(VDDAR_CORE)
VDD_CPU_AVS: C122.1 C123.1 C218.1 C219.1 C220.1 C221.1(INPUT) C221.3(OUTPUT) C231.1(INPUT) C231.3(OUTPUT) C232.1(INPUT) C232.3(OUTPUT) C234.1 C246.1 C247.1(INPUT) C247.3(OUTPUT) C248.1(INPUT) C248.3(OUTPUT) C254.1 C255.1(INPUT) C255.3(OUTPUT) C256.1 C257.1 C265.1(INPUT) C265.3(OUTPUT) C595.1(INPUT) C595.3(OUTPUT) C614.1(INPUT) C614.3(OUTPUT) C642.1 C651.1 C655.1 C663.1 C665.1 C668.1 C677.1 C692.1 C699.1 U37.N10(VDD_CPU) U37.P11(VDD_CPU) U37.R10(VDD_CPU) U37.R12(VDD_CPU) U37.U10(VDD_CPU) U37.V9(VDD_CPU) U37.V11(VDD_CPU) U37.W10(VDD_CPU) ; also on sheet 23
VDD_CPU_RAM_0V85: C149.1 C155.1 C643.1 C714.1 FL6.2 U37.L11(VDDAR_CPU) U37.W12(VDDAR_CPU)
VDD_DDR_1V1: C271.1 C275.1(INPUT) C275.3(OUTPUT) C282.1(INPUT) C282.3(OUTPUT) C288.1 C291.1 C294.1 C304.1 C306.1 C309.1 C314.1(INPUT) C314.3(OUTPUT) C317.1(INPUT) C317.3(OUTPUT) C318.1(INPUT) C318.3(OUTPUT) C322.1(INPUT) C322.3(OUTPUT) C323.1(INPUT) C323.3(OUTPUT) C328.1 C329.1 C331.1 C334.1(INPUT) C334.3(OUTPUT) C335.1(INPUT) C335.3(OUTPUT) C336.1(INPUT) C336.3(OUTPUT) C670.1 C671.1 C684.1 C689.1 C698.1 C706.1 C709.1 C716.1 C725.1 C735.1 C739.1 C745.1 C755.1 C763.1 U37.A1(VDDS_DDR) U37.G8(VDDS_DDR) U37.H7(VDDS_DDR_BIAS) U37.J6(VDDS_DDR_BIAS) U37.J8(VDDS_DDR) U37.K7(VDDS_DDR) U37.L8(VDDS_DDR) U37.M7(VDDS_DDR) U37.M9(VDDS_DDR_C) U37.N8(VDDS_DDR) U37.P7(VDDS_DDR) U37.R6(VDDS_DDR_BIAS) U37.R8(VDDS_DDR) U37.T1(VDDS_DDR) U37.T7(VDDS_DDR_BIAS) ; also on sheet 11 23 24
VDD_IO_1V8: C204.1(INPUT) C204.3(OUTPUT) C205.1(INPUT) C205.3(OUTPUT) C620.1 C628.1 U37.AA8(VDDS_MMC0) U37.AB7(VDDS_MMC0) U37.Y7(VDDS_MMC0) ; also on sheet 24 27
VDD_IO_3V3: C170.1(INPUT) C170.3(OUTPUT) C171.1(INPUT) C171.3(OUTPUT) C185.1(INPUT) C185.3(OUTPUT) C186.1(INPUT) C186.3(OUTPUT) C206.1(INPUT) C206.3(OUTPUT) C583.1 C584.1 C585.1 C586.1 C587.1 C588.1 C589.1 C590.1 C591.1 C598.1 C599.1 C600.1 C601.1 C602.1 C603.1 C604.1 C605.1 C618.1 C619.1 C621.1 C626.1 C629.1 C631.1 R73.2 R316.2 U37.AA17(VDDSHV2) U37.AA19(VDDSHV1) U37.AA20(VDDSHV1) U37.AA21(VDDSHV4) U37.AB16(VDDSHV2) U37.AB18(VDDSHV2) U37.AC17(VDDSHV2) U37.AC19(VDDSHV1) U37.AC20(VDDSHV1) U37.U8(VDDSHV0) U37.U20(VDDSHV6) U37.U22(VDDSHV6) U37.V7(VDDSHV0) U37.V21(VDDSHV3) U37.W22(VDDSHV3) U37.Y22(VDDSHV4) ; also on sheet 10 15 21 25 26 27 28 29 30 31 32 34 35 36 37 38 39 40
VDD_MCU_0V85: C324.1 C325.1 C326.1 C337.1(INPUT) C337.3(OUTPUT) C338.1(INPUT) C338.3(OUTPUT) C349.1(INPUT) C349.3(OUTPUT) C359.1(INPUT) C359.3(OUTPUT) C696.1 C703.1 C711.1 C712.1 C718.1 FL19.1 U37.L20(VDD_MCU) U37.M19(VDD_MCU) U37.M21(VDD_MCU) U37.N20(VDD_MCU) U37.P19(VDD_MCU) ; also on sheet 23
VDD_MCU_RAM_0V85: C360.1 C363.1 C724.1 FL19.2 U37.K19(VDDAR_MCU) U37.T19(VDDAR_MCU)
VDD_MCUIO_1V8: C339.1(INPUT) C339.3(OUTPUT) C740.1 C747.1 C773.1 U37.H19(VDDSHV1_MCU) U37.H21(VDDSHV1_MCU) U37.J20(VDDSHV1_MCU) ; also on sheet 12 23
VDD_MCUIO_3V3: C290.1(INPUT) C290.3(OUTPUT) C719.1 C723.1 C731.1 U37.J22(VDDSHV2_MCU) U37.K21(VDDSHV2_MCU) U37.L22(VDDSHV0_MCU) U37.M22(VDDSHV0_MCU) ; also on sheet 14 23 24 25 26 34 37 39
VDD_PHYIO_1V8: C610.1 FL7.1 FL8.1 FL18.1 U37.W7(VDDA_1P8_MLB) ; also on sheet 23
VDD_RAM_0V85: FL6.1 FL39.1 ; also on sheet 24
VDD_SD_DV: C667.1 U37.T20(VDDSHV5) U37.T22(VDDSHV5) ; also on sheet 24 36
VDDA_0P8_CSIRX: C351.1 C355.1 C741.1 C743.1 C744.1 C748.1 C752.1 C756.1 FL17.2 U37.G12(VDDA_0P8_DP) U37.G14(VDDA_0P8_DP_C) U37.H13(VDDA_0P8_DP_C) U37.H15(VDDA_0P8_DSITX) U37.H17(VDDA_0P8_CSIRX) U37.J12(VDDA_0P8_DP) U37.J16(VDDA_0P8_DSITX_C)
VDDA_0P8_DLL_MMC0: C191.1 C200.1 C633.1 C641.1 FL10.2 U37.W8(VDDA_0P8_PLL_MLB) U37.Y9(VDDA_0P8_DLL_MMC0)
VDDA_0P8_PLL_DDR: C342.1 C347.1 C704.1 FL15.2 U37.N9(VDDA_0P8_PLL_DDR)
VDDA_0P8_SERDES: C184.1 C196.1 C197.1 C198.1 C623.1 C624.1 C630.1 C632.1 C639.1 FL11.2 U37.AA12(VDDA_0P8_SERDES2_3) U37.AA15(VDDA_0P8_SERDES0_1) U37.AB12(VDDA_0P8_SERDES_C2_3) U37.AB13(VDDA_0P8_SERDES_C2_3) U37.AB14(VDDA_0P8_SERDES_C0_1) U37.AB15(VDDA_0P8_SERDES_C0_1) U37.Y11(VDDA_0P8_SERDES2_3) U37.Y13(VDDA_0P8_SERDES2_3) U37.Y14(VDDA_0P8_SERDES0_1) U37.Y16(VDDA_0P8_SERDES0_1)
VDDA_0P8_UFS: C182.1 C194.1 FL9.2 U37.AA10(VDDA_0P8_USB) U37.AB9(VDDA_0P8_UFS)
VDDA_1P8_CSI_RX: C352.1 C356.1 C738.1 C753.1 FL18.2 U37.G16(VDDA_1P8_CSIRX) U37.H11(VDDA_1P8_DP) U37.J14(VDDA_1P8_DSITX)
VDDA_1P8_SERDES: C156.1 C167.1 C615.1 C617.1 FL7.2 U37.AC11(VDDA_1P8_SERDES2_3) U37.AC12(VDDA_1P8_SERDES2_3) U37.AC14(VDDA_1P8_SERDES0_1) U37.AC15(VDDA_1P8_SERDES0_1)
VDDA_1P8_UFS: C162.1 C172.1 C616.1 FL8.2 U37.AC8(VDDA_1P8_UFS) U37.AC9(VDDA_1P8_USB)
A2B_GPIO_INTR_43: U37.AG25(PRG1_PRU1_GPO13) ; also on sheet 39
A2B_GPIO_INTR_77: U37.AJ25(PRG1_PRU1_GPO11) ; also on sheet 39
A2B_GPIO_OUT_57: U37.AH21(PRG1_PRU0_GPO19) ; also on sheet 39
A2B_GPIO_OUT_74: U37.AH25(PRG1_PRU1_GPO12) ; also on sheet 39
A2B_SPORT0_CLK: R109.2 ; also on sheet 39
A2B_SPORT0_D0: R209.1 U37.AD20(PRG1_PRU0_GPO5) ; also on sheet 39
A2B_SPORT0_D1: U37.AE20(PRG1_PRU0_GPO7) ; also on sheet 39
A2B_SPORT0_FS: R120.2 ; also on sheet 39
A2B_SPORT1_CLK: U37.AH24(PRG1_PRU1_GPO4) ; also on sheet 39
A2B_SPORT1_D0: U37.AD23(PRG1_PRU1_GPO3) ; also on sheet 39
A2B_SPORT1_FS: U37.AE23(PRG1_PRU1_GPO6) ; also on sheet 39
BOOTMODE0: R209.2 ; also on sheet 26
BOOTMODE1: R115.2 ; also on sheet 26
BOOTMODE2: U37.AC29(PRG0_PRU0_GPO5) ; also on sheet 26
BOOTMODE3: R128.2 ; also on sheet 26
BOOTMODE6: R100.2 ; also on sheet 26
BOOTMODE7: U37.AB24(PRG0_PRU0_GPO17) ; also on sheet 26
CHIMES_FSYNC: R116.2 ; also on sheet 32
CHIMES_M_SCLK: R122.2 ; also on sheet 32
CHIMES_nSTANDBY: U37.AH23(PRG1_PRU0_GPO4) ; also on sheet 32
CHIMES_SDIN: U37.AG24(PRG1_PRU0_GPO13) ; also on sheet 32
CHIMES_SDOUT: U37.AD24(PRG1_PRU0_GPO14) ; also on sheet 32
ENET_WAKE: U37.Y23(PRG1_PRU1_GPO8) ; also on sheet 37
I2C4_SCL: U37.AD19(PRG1_MDIO0_MDIO) ; also on sheet 38
I2C4_SDA: U37.AD18(PRG1_MDIO0_MDC) ; also on sheet 38
MCASP1_ACLKX_BOOTMODE6: R94.1 R100.1 U37.AB27(PRG0_PRU1_GPO5)
MCASP1_AFSX: R93.1 U37.AA28(PRG0_PRU1_GPO8)
MCASP2_AXR3_BOOTMODE3: R128.1 U37.Y25(PRG0_PRU1_GPO17)
MCASP3_ACLKX: R109.1 U37.AG20(PRG1_PRU0_GPO9)
MCASP3_AFSX: R120.1 U37.AD21(PRG1_PRU0_GPO10)
MCASP7_ACLKX: R122.1 U37.AF24(PRG1_PRU0_GPO11)
MCASP7_AFSX: R116.1 U37.AJ24(PRG1_PRU0_GPO12)
MMC_PWR_ON: U37.AG29(PRG0_PRU1_GPO16) ; also on sheet 36
PCIe0_RC_RSTz: U37.AJ26(PRG1_PRU1_GPO16) ; also on sheet 38
PCIe0_W_DISABLE#: U37.AJ27(PRG1_PRU1_GPO15) ; also on sheet 38
PCIe0_WAKE#: U37.AH26(PRG1_PRU1_GPO14) ; also on sheet 38
SEL_SDIO_3V3_1V8n: R73.1 U37.AH29(PRG0_PRU0_GPO13) ; also on sheet 24
SPI6_CLK_BOOTMODE1: R110.1 R115.1 U37.AC22(PRG1_PRU1_GPO17)
TPA6304_nSTANDBY: U37.AJ23(PRG1_PRU0_GPO3) ; also on sheet 32
TUNER0_IQ_ACLKR: U37.AE27(PRG0_PRU0_GPO2) ; also on sheet 35
TUNER0_IQ_AXR0: U37.AF28(PRG0_PRU0_GPO0) ; also on sheet 35
TUNER0_IQ_AXR1: U37.AE28(PRG0_PRU0_GPO1) ; also on sheet 35
TUNER0_IQ_FSR: U37.AD26(PRG0_PRU0_GPO3) ; also on sheet 35
TUNER1_IQ_ACLKR: U37.AA27(PRG0_MDIO0_MDC) ; also on sheet 35
TUNER1_IQ_AXR0: U37.AE25(PRG0_PRU1_GPO14) ; also on sheet 35
TUNER1_IQ_AXR1: U37.AF29(PRG0_PRU1_GPO15) ; also on sheet 35
TUNER1_IQ_FSR: U37.Y26(PRG0_MDIO0_MDIO) ; also on sheet 35
TUNER_AUDIO_ACLKX: R94.2 ; also on sheet 35
TUNER_AUDIO_AXR0: U37.AE29(PRG0_PRU1_GPO0) ; also on sheet 35
TUNER_AUDIO_AXR1: U37.AD28(PRG0_PRU1_GPO1) ; also on sheet 35
TUNER_AUDIO_AXR10: U37.AD27(PRG0_PRU1_GPO2) ; also on sheet 35
TUNER_AUDIO_AXR11: U37.AC25(PRG0_PRU1_GPO3) ; also on sheet 35
TUNER_AUDIO_FSX: R93.2 ; also on sheet 35
TUNER_SPI_CS0: U37.AC21(PRG1_PRU1_GPO7) ; also on sheet 35
TUNER_SPI_D0: U37.AJ22(PRG1_PRU1_GPO18) ; also on sheet 35
TUNER_SPI_D1: U37.AH22(PRG1_PRU1_GPO19) ; also on sheet 35
TUNER_SPI_SCLK: R110.2 ; also on sheet 35
VCAP_MCU_VDDS0: C732.1 U37.K23(CAP_VDDS0_MCU)
VCAP_MCU_VDDS1: C737.1 U37.J18(CAP_VDDS1_MCU)
VCAP_MCU_VDDS2: C742.1 U37.J19(CAP_VDDS2_MCU)
VCAP_VDDS0: C659.1 U37.U7(CAP_VDDS0)
VCAP_VDDS1: C622.1 U37.AB21(CAP_VDDS1)
VCAP_VDDS2: C638.1 U37.Y18(CAP_VDDS2)
VCAP_VDDS3: C640.1 U37.W21(CAP_VDDS3)
VCAP_VDDS4: C627.1 U37.AA22(CAP_VDDS4)
VCAP_VDDS5: C680.1 U37.R22(CAP_VDDS5)
VCAP_VDDS6: C658.1 U37.V22(CAP_VDDS6)
VDA_DLL_0V8: FL10.1 FL15.1 ; also on sheet 23
VDA_MCU_1V8: C675.1 C676.1 C678.1 C679.1 C700.1 U37.G18(VDDA_MCU_PLLGRP0) U37.H22(VDDA_WKUP) U37.M23(VDDA_ADC1) U37.N22(VDDA_ADC0) U37.P21(VDDA_MCU_TEMP) U37.P22(VDDA_POR_WKUP) ; also on sheet 23
VDA_PLL_1V8: C163.1 C173.1 C690.1 C691.1 C715.1 U37.H9(VDDA_TEMP2_3) U37.L12(VDDA_PLLGRP3) U37.M17(VDDA_PLLGRP2) U37.P9(VDDA_PLLGRP5) U37.R11(VDDA_PLLGRP4) U37.R21(VDDS_OSC1) U37.W15(VDDA_TEMP0_1) U37.W17(VDDA_PLLGRP1) U37.W18(VDDA_PLLGRP6) U37.Y20(VDDA_PLLGRP0) ; also on sheet 24
VDA_USB_3V3: C164.1 C174.1 U37.AB10(VDDA_3P3_USB) ; also on sheet 24
VMON_VEXT: TP39.1(TP) U37.V19(VMON_IR_VEXT)
VMON_VSYS: C297.1 R144.2 R145.1 U37.M26(VMON_ER_VSYS)
VPP_EFUSE_1V8: C207.1(INPUT) C207.3(OUTPUT) C208.1(INPUT) C208.3(OUTPUT) C625.1 C757.1 U37.AB11(VPP_CORE) U37.F17(VPP_MCU)
VSYS_3V3: R144.1 ; also on sheet 22 23 25 34 40
N23300995: R316.1 TP38.1 U37.AC18(EXTINTN)

Not connected (* = marked no-connect by the designer): U37 AA23(NC)* AA24(PRG0_PRU1_GPO7) AA25(PRG0_PRU1_GPO10) AA26(PRG0_PRU1_GPO18) AA29(PRG0_PRU1_GPO19) AB23(PRG1_PRU1_GPO10) AB25(PRG0_PRU0_GPO10) AB26(PRG0_PRU0_GPO9) AB28(PRG0_PRU0_GPO19) AB29(PRG0_PRU0_GPO18) AC23(PRG1_PRU0_GPO0) AC24(PRG1_PRU0_GPO15) AC26(PRG0_PRU1_GPO6) AC27(PRG0_PRU0_GPO8) AC28(PRG0_PRU0_GPO7) AD22(PRG1_PRU0_GPO6) AD25(PRG0_PRU0_GPO4) AD29(PRG0_PRU1_GPO4) AE21(PRG1_PRU0_GPO18) AE22(PRG1_PRU1_GPO0) AE24(PRG1_PRU0_GPO16) AE26(PRG0_PRU0_GPO6) AF21(PRG1_PRU1_GPO9) AF22(PRG1_PRU0_GPO2) AF23(PRG1_PRU1_GPO2) AF26(PRG0_PRU1_GPO13) AF27(PRG0_PRU1_GPO12) AG21(PRG1_PRU1_GPO5) AG22(PRG1_PRU0_GPO1) AG23(PRG1_PRU1_GPO1) AG26(PRG0_PRU1_GPO11) AG27(PRG0_PRU0_GPO15) AG28(PRG0_PRU0_GPO14) AH27(PRG0_PRU0_GPO12) AH28(PRG0_PRU0_GPO16) AJ20(PRG1_PRU0_GPO8) AJ21(PRG1_PRU0_GPO17) AJ28(PRG0_PRU0_GPO11) Y24(PRG0_PRU1_GPO9)

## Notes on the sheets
sheet 16
- PRG0 & PRG1
- GPIO0_0
sheet 17
- ANALOG POWER 1
- Vth(min) = 0.45V
sheet 18
- DIGITAL POWER 2
sheet 19
- DIGITAL POWER 3
sheet 20
- SOC GROUND
